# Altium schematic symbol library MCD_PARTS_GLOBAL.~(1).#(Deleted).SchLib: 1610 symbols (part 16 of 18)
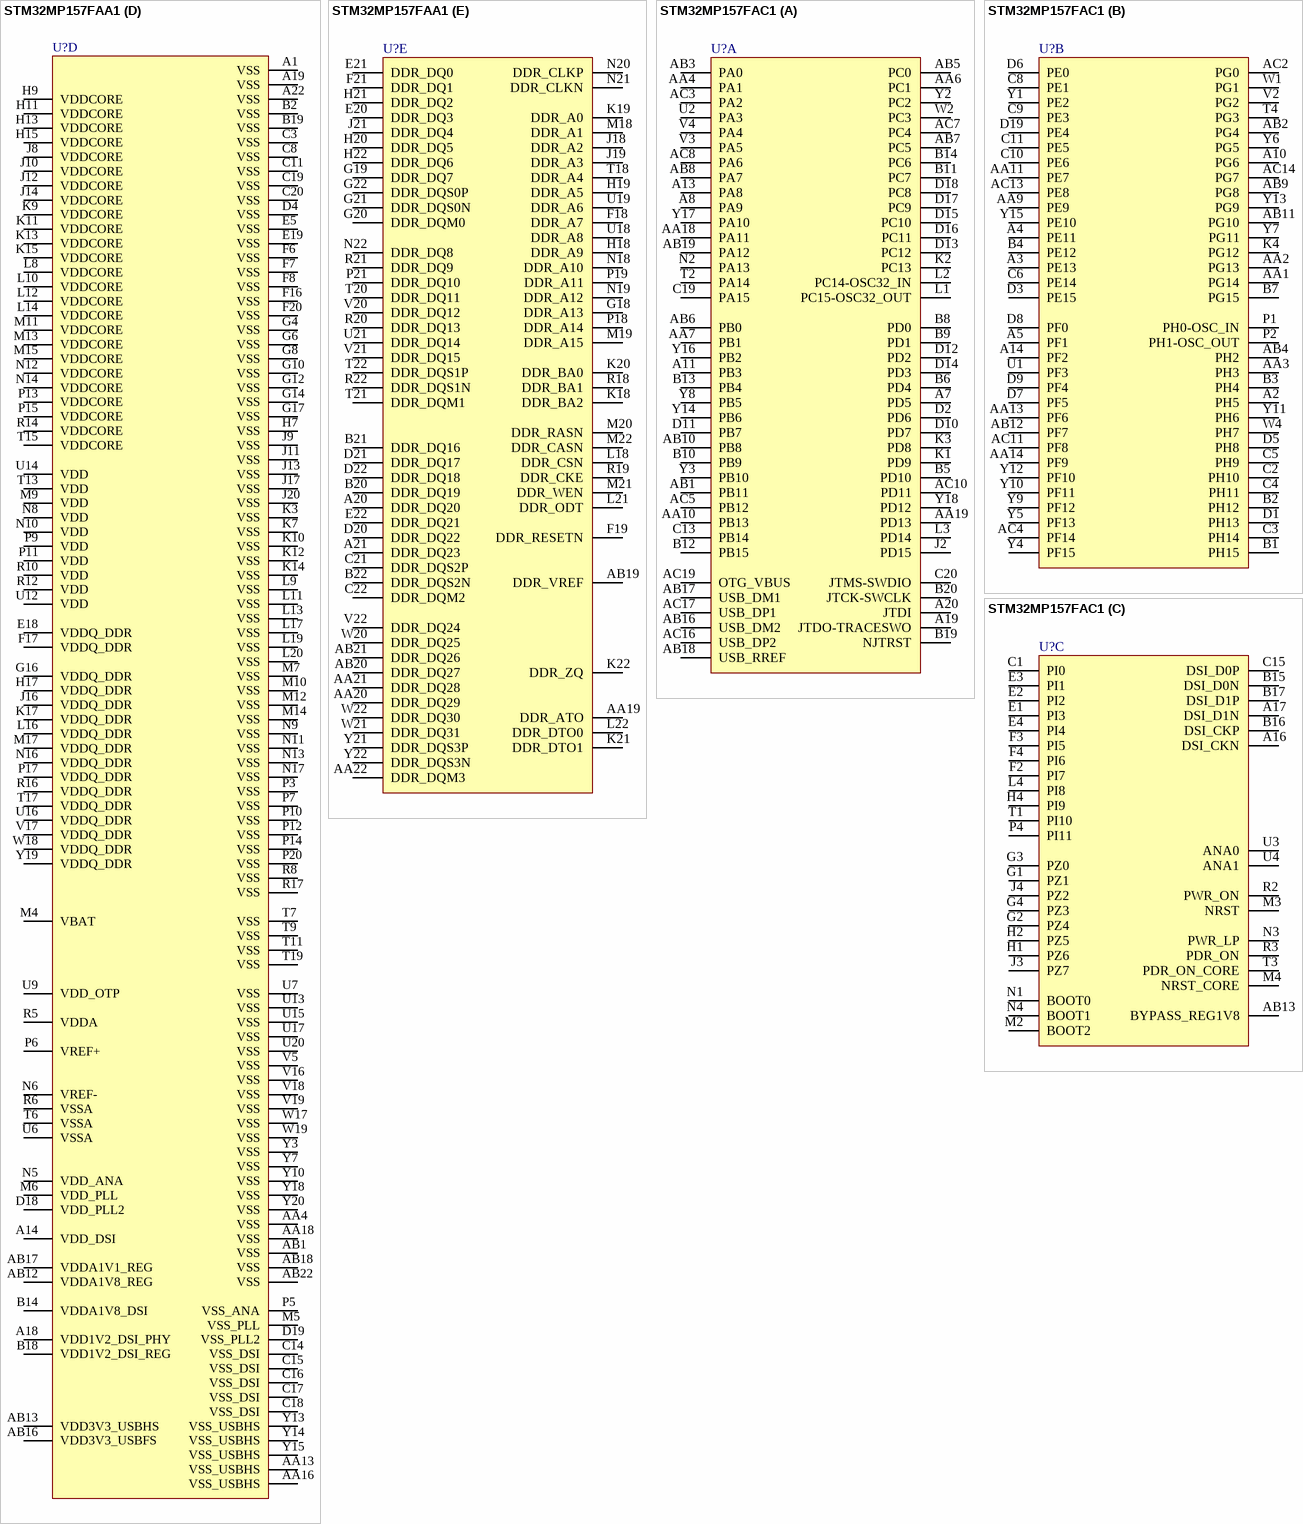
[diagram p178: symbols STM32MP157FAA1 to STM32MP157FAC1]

## STM32MP157FAA1
designator U?
part A pins: A8 PD10, A9 PD5, A11 PA9, A12 PB3, A13 PB14, AA3 PA0, AA5 PB1, AA6 PC5, AA7 PB12, AA8 PB5, AA14 USB_DM2, AA15 USB_DP1, AA17 USB_RREF, AB2 PA2, AB3 PC1, AB5 PB0, AB6 PC4, AB8 PB8, AB9 PD11, AB14 USB_DP2, AB15 USB_DM1, B10 PD1, B11 PD3, B12 PB15, B13 PA8, C9 PD4, C10 PD0, C13 PB4, D12 PD2, D13 PC7, D14 PC9, D15 PC11, D16 JTDI, D17 JTCK-SWCLK, E11 PA15, E12 PC12, E13 PC6, E14 PC8, E15 NJTRST, E16 JTDO-TRACESWO, E17 JTMS-SWDIO, F10 PD7, F11 PB7, F12 PB9, F14 PC10, L1 PD15, L3 PD6, M1 PD8, M2 PD9, M3 PD14, N2 PC13, P1 PC14-OSC32_IN, P2 PC15-OSC32_OUT, R3 PA14, T4 PA3, U3 PC3, U5 PA5, U10 PC0, V4 PA1, V6 PA4, V9 PB10, V10 PB13, V13 PB2, V14 PD13, V15 USBO_VBUS, W3 PA13, W9 PA6, W12 PD12, W13 PB6, W16 PA12, Y1 PC2, Y5 PB11, Y9 PA7, Y16 PA11, Y17 PA10
part B pins: A2 PH5, A3 PH4, A4 PE13, A10 PE3, AA1 PG13, AA2 PG14, AA9 PG10, AA10 PF7, AA11 PF6, AB4 PG4, AB7 PH2, AB10 PF8, AB11 PF9, B1 PH10, B3 PH11, B4 PE14, B9 PF1, C1 PH15, C2 PH14, C4 PE15, C5 PE0, C12 PE5, D3 PH13, D5 PE11, D6 PH8, D7 PE1, D9 PF5, D10 PG15, D11 PG6, E4 PE12, E6 PH9, E9 PE6, E10 PF0, F5 PH12, F9 PF4, F13 PF2, F15 PE4, J4 PG12, T1 PH0-OSC_IN, T2 PH1-OSC_OUT, U4 PG3, U8 PG5, U11 PG11, V3 PF3, V7 PF14, V8 PF12, V11 PH6, V12 PF10, W2 PH7, W4 PG2, W5 PG0, W6 PF15, W7 PF13, W8 PF11, W10 PE7, W11 PE9, W14 PE10, W15 PG9, Y2 PE2, Y4 PG1, Y6 PH3, Y8 PG8, Y11 PG7, Y12 PE8
part C pins: A5 PK6, A6 PK4, A7 PJ13, A15 DSI_D0_N, A16 DSI_CK_N, A17 DSI_D1_N, AA12 BYPASS_REG1V8, B5 PK7, B6 PK3, B7 PJ14, B8 PJ12, B15 DSI_D0_P, B16 DSI_CK_P, B17 DSI_D1_P, C6 PK5, C7 PJ15, D1 PI0, D2 PI14, D8 PK0, E1 PI2, E2 PI1, E3 PI3, E7 PK1, E8 PK2, F1 PI7, F2 PI5, F3 PI15, F4 PZ3, G1 PZ4, G2 PZ0, G3 PZ6, G5 PI6, H1 PI13, H2 PI12, H3 PZ7, H4 PZ5, H5 PZ1, H6 PJ8, J1 PJ3, J2 PJ0, J3 PJ10, J5 PI9, J6 PI4, K1 PJ5, K2 PJ4, K4 PJ2, K5 PZ2, K6 PJ11, L2 PJ9, L4 PJ7, L5 PJ6, L6 PJ1, N1 PI8, N3 BOOT0, N4 BOOT1, P4 BOOT2, R1 NRST_CORE, R2 NRST, R4 ANA0, T3 PI11, T5 ANA1, U1 PWR_LP, U2 PDR_ON_CORE, V1 PWR_ON, V2 PDR_ON, W1 PI10
part D pins: A1 VSS, A14 VDD_DSI, A18 VDD1V2_DSI_PHY, A19 VSS, A22 VSS, AA4 VSS, AA13 VSS_USBHS, AA16 VSS_USBHS, AA18 VSS, AB1 VSS, AB12 VDDA1V8_REG, AB13 VDD3V3_USBHS, AB16 VDD3V3_USBFS, AB17 VDDA1V1_REG, AB18 VSS, AB22 VSS, B2 VSS, B14 VDDA1V8_DSI, B18 VDD1V2_DSI_REG, B19 VSS, C3 VSS, C8 VSS, C11 VSS, C14 VSS_DSI, C15 VSS_DSI, C16 VSS_DSI, C17 VSS_DSI, C18 VSS_DSI, C19 VSS, C20 VSS, D4 VSS, D18 VDD_PLL2, D19 VSS_PLL2, E5 VSS, E18 VDDQ_DDR, E19 VSS, F6 VSS, F7 VSS, F8 VSS, F16 VSS, F17 VDDQ_DDR, F20 VSS, G4 VSS, G6 VSS, G8 VSS, G10 VSS, G12 VSS, G14 VSS, G16 VDDQ_DDR, G17 VSS, H7 VSS, H9 VDDCORE, H11 VDDCORE, H13 VDDCORE, H15 VDDCORE, H17 VDDQ_DDR, J8 VDDCORE, J9 VSS, J10 VDDCORE, J11 VSS, J12 VDDCORE, J13 VSS, J14 VDDCORE, J16 VDDQ_DDR, J17 VSS, J20 VSS, K3 VSS, K7 VSS, K9 VDDCORE, K10 VSS, K11 VDDCORE, K12 VSS, K13 VDDCORE, K14 VSS, K15 VDDCORE, K17 VDDQ_DDR, L8 VDDCORE, L9 VSS, L10 VDDCORE, L11 VSS, L12 VDDCORE, L13 VSS, L14 VDDCORE, L16 VDDQ_DDR, L17 VSS, L19 VSS, L20 VSS, M4 VBAT, M5 VSS_PLL, M6 VDD_PLL, M7 VSS, M9 VDD, M10 VSS, M11 VDDCORE, M12 VSS, M13 VDDCORE, M14 VSS, M15 VDDCORE, M17 VDDQ_DDR, N5 VDD_ANA, N6 VREF-, N8 VDD, N9 VSS, N10 VDD, N11 VSS, N12 VDDCORE, N13 VSS, N14 VDDCORE, N16 VDDQ_DDR, N17 VSS, P3 VSS, P5 VSS_ANA, P6 VREF+, P7 VSS, P9 VDD, P10 VSS, P11 VDD, P12 VSS, P13 VDDCORE, P14 VSS, P15 VDDCORE, P17 VDDQ_DDR, P20 VSS, R5 VDDA, R6 VSSA, R8 VSS, R10 VDD, R12 VDD, R14 VDDCORE, R16 VDDQ_DDR, R17 VSS, T6 VSSA, T7 VSS, T9 VSS, T11 VSS, T13 VDD, T15 VDDCORE, T17 VDDQ_DDR, T19 VSS, U6 VSSA, U7 VSS, U9 VDD_OTP, U12 VDD, U13 VSS, U14 VDD, U15 VSS, U16 VDDQ_DDR, U17 VSS, U20 VSS, V5 VSS, V16 VSS, V17 VDDQ_DDR, V18 VSS, V19 VSS, W17 VSS, W18 VDDQ_DDR, W19 VSS, Y3 VSS, Y7 VSS, Y10 VSS, Y13 VSS_USBHS, Y14 VSS_USBHS, Y15 VSS_USBHS, Y18 VSS, Y19 VDDQ_DDR, Y20 VSS
part E pins: A20 DDR_DQ20, A21 DDR_DQ23, AA19 DDR_ATO, AA20 DDR_DQ29, AA21 DDR_DQ28, AA22 DDR_DQM3, AB19 DDR_VREF, AB20 DDR_DQ27, AB21 DDR_DQ26, B20 DDR_DQ19, B21 DDR_DQ16, B22 DDR_DQS2N, C21 DDR_DQS2P, C22 DDR_DQM2, D20 DDR_DQ22, D21 DDR_DQ17, D22 DDR_DQ18, E20 DDR_DQ3, E21 DDR_DQ0, E22 DDR_DQ21, F18 DDR_A7, F19 DDR_RESETN, F21 DDR_DQ1, G18 DDR_A13, G19 DDR_DQ7, G20 DDR_DQM0, G21 DDR_DQS0N, G22 DDR_DQS0P, H18 DDR_A9, H19 DDR_A5, H20 DDR_DQ5, H21 DDR_DQ2, H22 DDR_DQ6, J18 DDR_A2, J19 DDR_A3, J21 DDR_DQ4, K18 DDR_BA2, K19 DDR_A0, K20 DDR_BA0, K21 DDR_DTO1, K22 DDR_ZQ, L18 DDR_CSN, L21 DDR_ODT, L22 DDR_DTO0, M18 DDR_A1, M19 DDR_A15, M20 DDR_RASN, M21 DDR_WEN, M22 DDR_CASN, N18 DDR_A10, N19 DDR_A12, N20 DDR_CLKP, N21 DDR_CLKN, N22 DDR_DQ8, P18 DDR_A14, P19 DDR_A11, P21 DDR_DQ10, R18 DDR_BA1, R19 DDR_CKE, R20 DDR_DQ13, R21 DDR_DQ9, R22 DDR_DQS1N, T18 DDR_A4, T20 DDR_DQ11, T21 DDR_DQM1, T22 DDR_DQS1P, U18 DDR_A8, U19 DDR_A6, U21 DDR_DQ14, V20 DDR_DQ12, V21 DDR_DQ15, V22 DDR_DQ24, W20 DDR_DQ25, W21 DDR_DQ31, W22 DDR_DQ30, Y21 DDR_DQS3P, Y22 DDR_DQS3N

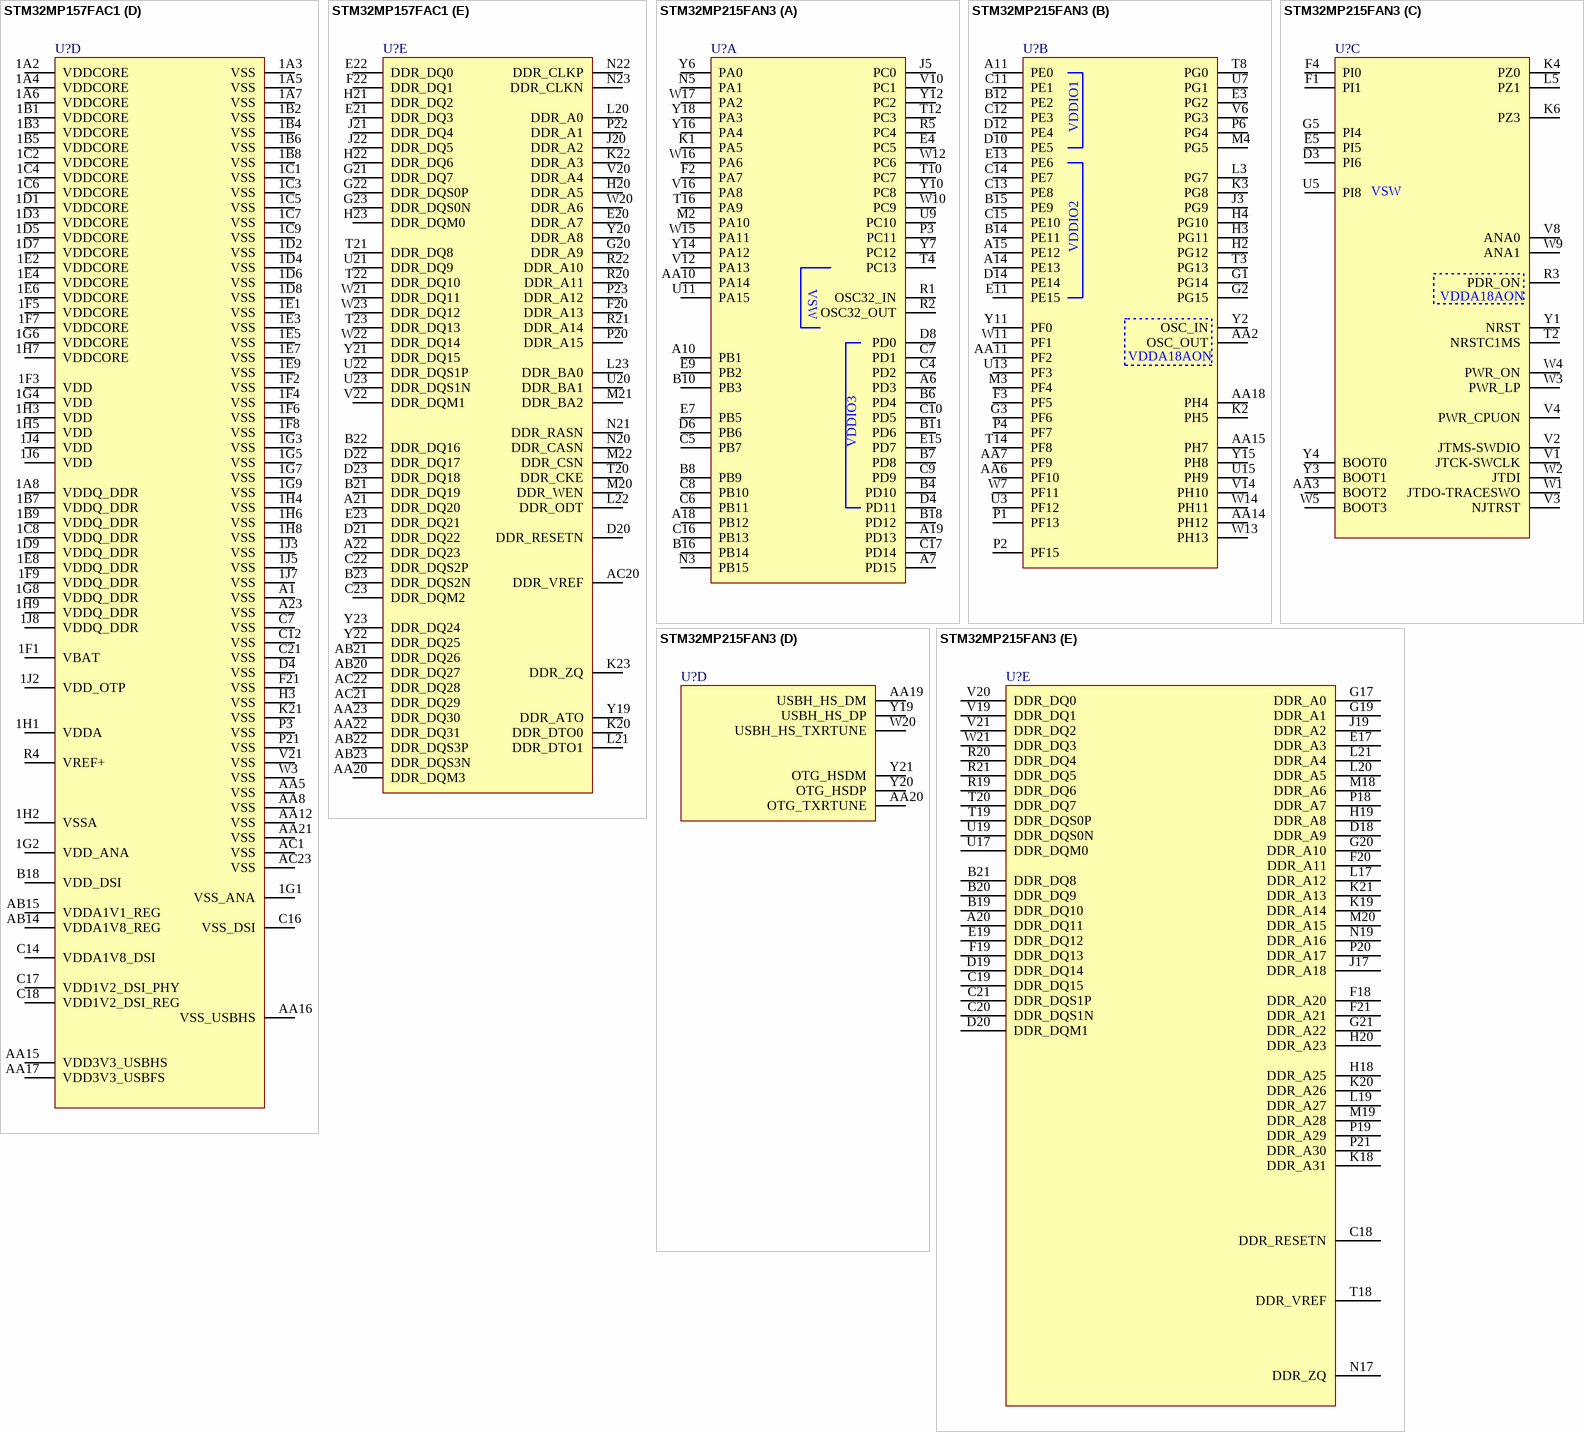
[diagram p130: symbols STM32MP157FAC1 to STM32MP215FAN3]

## STM32MP157FAC1
designator U?
part A pins: A7 PD5, A8 PA9, A11 PB3, A13 PA8, A19 JTDO-TRACESWO, A20 JTDI, AA4 PA1, AA6 PC1, AA7 PB1, AA10 PB13, AA18 PA11, AA19 PD13, AB1 PB11, AB3 PA0, AB5 PC0, AB6 PB0, AB7 PC5, AB8 PA7, AB10 PB8, AB16 USB_DM2, AB17 USB_DM1, AB18 USB_RREF, AB19 PA12, AC3 PA2, AC5 PB12, AC7 PC4, AC8 PA6, AC10 PD11, AC16 USB_DP2, AC17 USB_DP1, AC19 OTG_VBUS, B5 PD10, B6 PD4, B8 PD0, B9 PD1, B10 PB9, B11 PC7, B12 PB15, B13 PB4, B14 PC6, B19 NJTRST, B20 JTCK-SWCLK, C13 PB14, C19 PA15, C20 JTMS-SWDIO, D2 PD6, D10 PD7, D11 PB7, D12 PD2, D13 PC12, D14 PD3, D15 PC10, D16 PC11, D17 PC9, D18 PC8, J2 PD15, K1 PD9, K2 PC13, K3 PD8, L1 PC15-OSC32_OUT, L2 PC14-OSC32_IN, L3 PD14, N2 PA13, T2 PA14, U2 PA3, V3 PA5, V4 PA4, W2 PC3, Y2 PC2, Y3 PB10, Y8 PB5, Y14 PB6, Y16 PB2, Y17 PA10, Y18 PD12
part B pins: A2 PH5, A3 PE13, A4 PE11, A5 PF1, A10 PG6, A14 PF2, AA1 PG14, AA2 PG13, AA3 PH3, AA9 PE9, AA11 PE7, AA13 PF6, AA14 PF9, AB2 PG4, AB4 PH2, AB9 PG8, AB11 PG10, AB12 PF7, AC2 PG0, AC4 PF14, AC11 PF8, AC13 PE8, AC14 PG7, B1 PH15, B2 PH12, B3 PH4, B4 PE12, B7 PG15, C2 PH10, C3 PH14, C4 PH11, C5 PH9, C6 PE14, C8 PE1, C9 PE3, C10 PE6, C11 PE5, D1 PH13, D3 PE15, D5 PH8, D6 PE0, D7 PF5, D8 PF0, D9 PF4, D19 PE4, K4 PG12, P1 PH0-OSC_IN, P2 PH1-OSC_OUT, T4 PG3, U1 PF3, V2 PG2, W1 PG1, W4 PH7, Y1 PE2, Y4 PF15, Y5 PF13, Y6 PG5, Y7 PG11, Y9 PF12, Y10 PF11, Y11 PH6, Y12 PF10, Y13 PG9, Y15 PE10
part C pins: A16 DSI_CKN, A17 DSI_D1N, AB13 BYPASS_REG1V8, B15 DSI_D0N, B16 DSI_CKP, B17 DSI_D1P, C1 PI0, C15 DSI_D0P, E1 PI3, E2 PI2, E3 PI1, E4 PI4, F2 PI7, F3 PI5, F4 PI6, G1 PZ1, G2 PZ4, G3 PZ0, G4 PZ3, H1 PZ6, H2 PZ5, H4 PI9, J3 PZ7, J4 PZ2, L4 PI8, M2 BOOT2, M3 NRST, M4 NRST_CORE, N1 BOOT0, N3 PWR_LP, N4 BOOT1, P4 PI11, R2 PWR_ON, R3 PDR_ON, T1 PI10, T3 PDR_ON_CORE, U3 ANA0, U4 ANA1
part D pins: 1A2 VDDCORE, 1A3 VSS, 1A4 VDDCORE, 1A5 VSS, 1A6 VDDCORE, 1A7 VSS, 1A8 VDDQ_DDR, 1B1 VDDCORE, 1B2 VSS, 1B3 VDDCORE, 1B4 VSS, 1B5 VDDCORE, 1B6 VSS, 1B7 VDDQ_DDR, 1B8 VSS, 1B9 VDDQ_DDR, 1C1 VSS, 1C2 VDDCORE, 1C3 VSS, 1C4 VDDCORE, 1C5 VSS, 1C6 VDDCORE, 1C7 VSS, 1C8 VDDQ_DDR, 1C9 VSS, 1D1 VDDCORE, 1D2 VSS, 1D3 VDDCORE, 1D4 VSS, 1D5 VDDCORE, 1D6 VSS, 1D7 VDDCORE, 1D8 VSS, 1D9 VDDQ_DDR, 1E1 VSS, 1E2 VDDCORE, 1E3 VSS, 1E4 VDDCORE, 1E5 VSS, 1E6 VDDCORE, 1E7 VSS, 1E8 VDDQ_DDR, 1E9 VSS, 1F1 VBAT, 1F2 VSS, 1F3 VDD, 1F4 VSS, 1F5 VDDCORE, 1F6 VSS, 1F7 VDDCORE, 1F8 VSS, 1F9 VDDQ_DDR, 1G1 VSS_ANA, 1G2 VDD_ANA, 1G3 VSS, 1G4 VDD, 1G5 VSS, 1G6 VDDCORE, 1G7 VSS, 1G8 VDDQ_DDR, 1G9 VSS, 1H1 VDDA, 1H2 VSSA, 1H3 VDD, 1H4 VSS, 1H5 VDD, 1H6 VSS, 1H7 VDDCORE, 1H8 VSS, 1H9 VDDQ_DDR, 1J2 VDD_OTP, 1J3 VSS, 1J4 VDD, 1J5 VSS, 1J6 VDD, 1J7 VSS, 1J8 VDDQ_DDR, A1 VSS, A23 VSS, AA5 VSS, AA8 VSS, AA12 VSS, AA15 VDD3V3_USBHS, AA16 VSS_USBHS, AA17 VDD3V3_USBFS, AA21 VSS, AB14 VDDA1V8_REG, AB15 VDDA1V1_REG, AC1 VSS, AC23 VSS, B18 VDD_DSI, C7 VSS, C12 VSS, C14 VDDA1V8_DSI, C16 VSS_DSI, C17 VDD1V2_DSI_PHY, C18 VDD1V2_DSI_REG, C21 VSS, D4 VSS, F21 VSS, H3 VSS, K21 VSS, P3 VSS, P21 VSS, R4 VREF+, V21 VSS, W3 VSS
part E pins: A21 DDR_DQ20, A22 DDR_DQ23, AA20 DDR_DQM3, AA22 DDR_DQ31, AA23 DDR_DQ30, AB20 DDR_DQ27, AB21 DDR_DQ26, AB22 DDR_DQS3P, AB23 DDR_DQS3N, AC20 DDR_VREF, AC21 DDR_DQ29, AC22 DDR_DQ28, B21 DDR_DQ19, B22 DDR_DQ16, B23 DDR_DQS2N, C22 DDR_DQS2P, C23 DDR_DQM2, D20 DDR_RESETN, D21 DDR_DQ22, D22 DDR_DQ17, D23 DDR_DQ18, E20 DDR_A7, E21 DDR_DQ3, E22 DDR_DQ0, E23 DDR_DQ21, F20 DDR_A13, F22 DDR_DQ1, G20 DDR_A9, G21 DDR_DQ7, G22 DDR_DQS0P, G23 DDR_DQS0N, H20 DDR_A5, H21 DDR_DQ2, H22 DDR_DQ6, H23 DDR_DQM0, J20 DDR_A2, J21 DDR_DQ4, J22 DDR_DQ5, K20 DDR_DTO0, K22 DDR_A3, K23 DDR_ZQ, L20 DDR_A0, L21 DDR_DTO1, L22 DDR_ODT, L23 DDR_BA0, M20 DDR_WEN, M21 DDR_BA2, M22 DDR_CSN, N20 DDR_CASN, N21 DDR_RASN, N22 DDR_CLKP, N23 DDR_CLKN, P20 DDR_A15, P22 DDR_A1, P23 DDR_A12, R20 DDR_A11, R21 DDR_A14, R22 DDR_A10, T20 DDR_CKE, T21 DDR_DQ8, T22 DDR_DQ10, T23 DDR_DQ13, U20 DDR_BA1, U21 DDR_DQ9, U22 DDR_DQS1P, U23 DDR_DQS1N, V20 DDR_A4, V22 DDR_DQM1, W20 DDR_A6, W21 DDR_DQ11, W22 DDR_DQ14, W23 DDR_DQ12, Y19 DDR_ATO, Y20 DDR_A8, Y21 DDR_DQ15, Y22 DDR_DQ25, Y23 DDR_DQ24

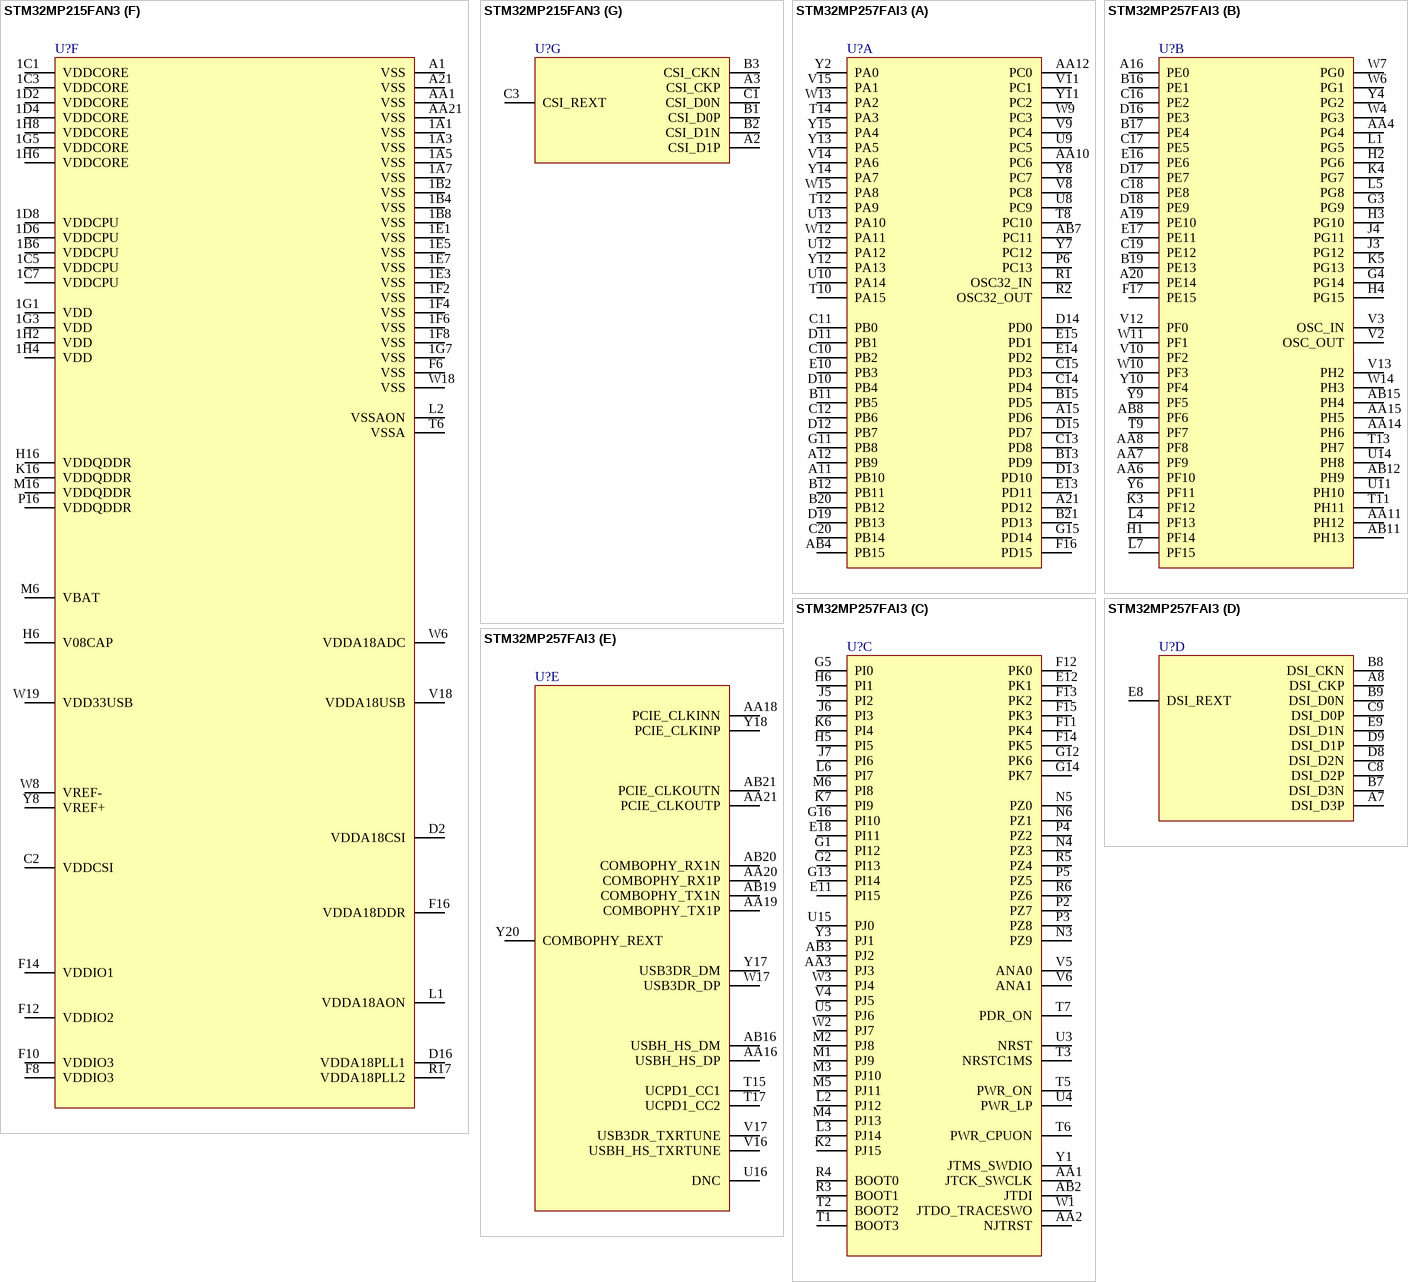
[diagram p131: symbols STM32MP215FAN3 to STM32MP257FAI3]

## STM32MP215FAN3
designator U?
part A pins: A6 PD3, A7 PD15, A10 PB1, A18 PB12, A19 PD13, AA10 PA14, B4 PD10, B6 PD4, B7 PD8, B8 PB9, B10 PB3, B11 PD6, B16 PB14, B18 PD12, C4 PD2, C5 PB7, C6 PB11, C7 PD1, C8 PB10, C9 PD9, C10 PD5, C16 PB13, C17 PD14, D4 PD11, D6 PB6, D8 PD0, E4 PC5, E7 PB5, E9 PB2, E15 PD7, F2 PA7, J5 PC0, K1 PA5, M2 PA10, N3 PB15, N5 PA1, P3 PC11, R1 OSC32_IN, R2 OSC32_OUT, R5 PC4, T4 PC13, T10 PC7, T12 PC3, T16 PA9, U9 PC10, U11 PA15, V10 PC1, V12 PA13, V16 PA8, W10 PC9, W12 PC6, W15 PA11, W16 PA6, W17 PA2, Y6 PA0, Y7 PC12, Y10 PC8, Y12 PC2, Y14 PA12, Y16 PA4, Y18 PA3
part B pins: A11 PE0, A14 PE13, A15 PE12, AA2 OSC_OUT, AA6 PF10, AA7 PF9, AA11 PF2, AA14 PH12, AA15 PH7, AA18 PH4, B12 PE2, B14 PE11, B15 PE9, C11 PE1, C12 PE3, C13 PE8, C14 PE7, C15 PE10, D10 PE5, D12 PE4, D14 PE14, E3 PG2, E11 PE15, E13 PE6, F3 PF5, G1 PG14, G2 PG15, G3 PF6, H2 PG12, H3 PG11, H4 PG10, J3 PG9, K2 PH5, K3 PG8, L3 PG7, M3 PF4, M4 PG5, P1 PF13, P2 PF15, P4 PF7, P6 PG4, T3 PG13, T8 PG0, T14 PF8, U3 PF12, U7 PG1, U13 PF3, U15 PH9, V6 PG3, V14 PH10, W7 PF11, W11 PF1, W13 PH13, W14 PH11, Y2 OSC_IN, Y11 PF0, Y15 PH8
part C pins: AA3 BOOT2, D3 PI6, E5 PI5, F1 PI1, F4 PI0, G5 PI4, K4 PZ0, K6 PZ3, L5 PZ1, R3 PDR_ON, T2 NRSTC1MS, U5 PI8, V1 JTCK-SWCLK, V2 JTMS-SWDIO, V3 NJTRST, V4 PWR_CPUON, V8 ANA0, W1 JTDO-TRACESWO, W2 JTDI, W3 PWR_LP, W4 PWR_ON, W5 BOOT3, W9 ANA1, Y1 NRST, Y3 BOOT1, Y4 BOOT0
part D pins: AA19 USBH_HS_DM, AA20 OTG_TXRTUNE, W20 USBH_HS_TXRTUNE, Y19 USBH_HS_DP, Y20 OTG_HSDP, Y21 OTG_HSDM
part E pins: A20 DDR_DQ11, B19 DDR_DQ10, B20 DDR_DQ9, B21 DDR_DQ8, C18 DDR_RESETN, C19 DDR_DQ15, C20 DDR_DQS1N, C21 DDR_DQS1P, D18 DDR_A9, D19 DDR_DQ14, D20 DDR_DQM1, E17 DDR_A3, E19 DDR_DQ12, F18 DDR_A20, F19 DDR_DQ13, F20 DDR_A11, F21 DDR_A21, G17 DDR_A0, G19 DDR_A1, G20 DDR_A10, G21 DDR_A22, H18 DDR_A25, H19 DDR_A8, H20 DDR_A23, J17 DDR_A18, J19 DDR_A2, K18 DDR_A31, K19 DDR_A14, K20 DDR_A26, K21 DDR_A13, L17 DDR_A12, L19 DDR_A27, L20 DDR_A5, L21 DDR_A4, M18 DDR_A6, M19 DDR_A28, M20 DDR_A15, N17 DDR_ZQ, N19 DDR_A16, P18 DDR_A7, P19 DDR_A29, P20 DDR_A17, P21 DDR_A30, R19 DDR_DQ6, R20 DDR_DQ4, R21 DDR_DQ5, T18 DDR_VREF, T19 DDR_DQS0P, T20 DDR_DQ7, U17 DDR_DQM0, U19 DDR_DQS0N, V19 DDR_DQ1, V20 DDR_DQ0, V21 DDR_DQ2, W21 DDR_DQ3
part F pins: 1A1 VSS, 1A3 VSS, 1A5 VSS, 1A7 VSS, 1B2 VSS, 1B4 VSS, 1B6 VDDCPU, 1B8 VSS, 1C1 VDDCORE, 1C3 VDDCORE, 1C5 VDDCPU, 1C7 VDDCPU, 1D2 VDDCORE, 1D4 VDDCORE, 1D6 VDDCPU, 1D8 VDDCPU, 1E1 VSS, 1E3 VSS, 1E5 VSS, 1E7 VSS, 1F2 VSS, 1F4 VSS, 1F6 VSS, 1F8 VSS, 1G1 VDD, 1G3 VDD, 1G5 VDDCORE, 1G7 VSS, 1H2 VDD, 1H4 VDD, 1H6 VDDCORE, 1H8 VDDCORE, A1 VSS, A21 VSS, AA1 VSS, AA21 VSS, C2 VDDCSI, D2 VDDA18CSI, D16 VDDA18PLL1, F6 VSS, F8 VDDIO3, F10 VDDIO3, F12 VDDIO2, F14 VDDIO1, F16 VDDA18DDR, H6 V08CAP, H16 VDDQDDR, K16 VDDQDDR, L1 VDDA18AON, L2 VSSAON, M6 VBAT, M16 VDDQDDR, P16 VDDQDDR, R17 VDDA18PLL2, T6 VSSA, V18 VDDA18USB, W6 VDDA18ADC, W8 VREF-, W18 VSS, W19 VDD33USB, Y8 VREF+
part G pins: A2 CSI_D1P, A3 CSI_CKP, B1 CSI_D0P, B2 CSI_D1N, B3 CSI_CKN, C1 CSI_D0N, C3 CSI_REXT

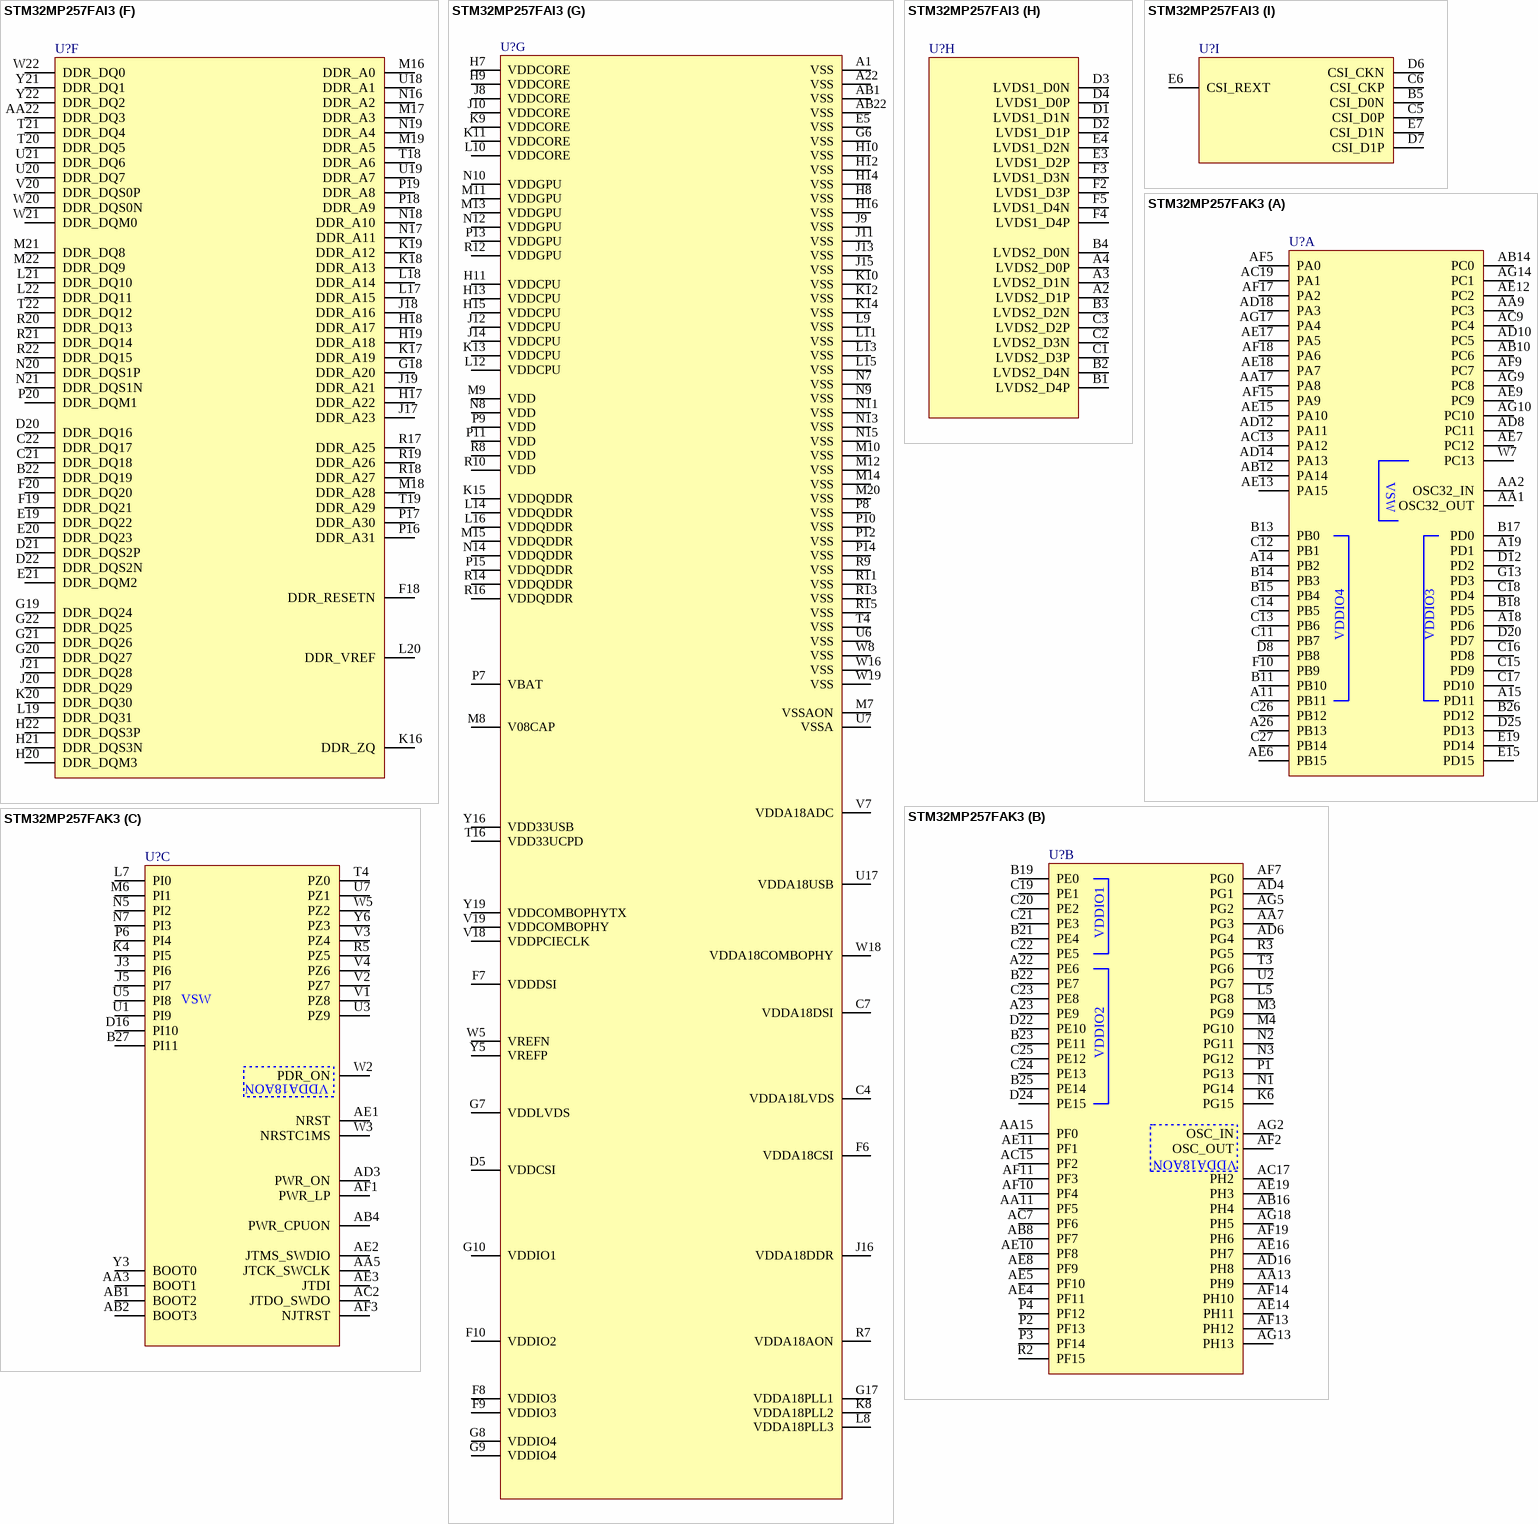
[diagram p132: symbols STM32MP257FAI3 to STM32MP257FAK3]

## STM32MP257FAI3
designator U?
part A pins: A11 PB10, A12 PB9, A15 PD6, A21 PD12, AA10 PC6, AA12 PC0, AB4 PB15, AB7 PC11, B11 PB5, B12 PB11, B13 PD9, B15 PD5, B20 PB12, B21 PD13, C10 PB2, C11 PB0, C12 PB6, C13 PD8, C14 PD4, C15 PD3, C20 PB14, D10 PB4, D11 PB1, D12 PB7, D13 PD10, D14 PD0, D15 PD7, D19 PB13, E10 PB3, E13 PD11, E14 PD2, E15 PD1, F16 PD15, G11 PB8, G15 PD14, P6 PC13, R1 OSC32_IN, R2 OSC32_OUT, T8 PC10, T10 PA15, T12 PA9, T14 PA3, U8 PC9, U9 PC5, U10 PA14, U12 PA12, U13 PA10, V8 PC8, V9 PC4, V11 PC1, V14 PA6, V15 PA1, W9 PC3, W12 PA11, W13 PA2, W15 PA8, Y2 PA0, Y7 PC12, Y8 PC7, Y11 PC2, Y12 PA13, Y13 PA5, Y14 PA7, Y15 PA4
part B pins: A16 PE0, A19 PE10, A20 PE14, AA4 PG4, AA6 PF10, AA7 PF9, AA8 PF8, AA11 PH12, AA14 PH6, AA15 PH5, AB8 PF6, AB11 PH13, AB12 PH9, AB15 PH4, B16 PE1, B17 PE4, B19 PE13, C16 PE2, C17 PE5, C18 PE8, C19 PE12, D16 PE3, D17 PE7, D18 PE9, E16 PE6, E17 PE11, F17 PE15, G3 PG9, G4 PG14, H1 PF14, H2 PG6, H3 PG10, H4 PG15, J3 PG12, J4 PG11, K3 PF12, K4 PG7, K5 PG13, L1 PG5, L4 PF13, L5 PG8, L7 PF15, T9 PF7, T11 PH11, T13 PH7, U11 PH10, U14 PH8, V2 OSC_OUT, V3 OSC_IN, V10 PF2, V12 PF0, V13 PH2, W4 PG3, W6 PG1, W7 PG0, W10 PF3, W11 PF1, W14 PH3, Y4 PG2, Y6 PF11, Y9 PF5, Y10 PF4
part C pins: AA1 JTCK_SWCLK, AA2 NJTRST, AA3 PJ3, AB2 JTDI, AB3 PJ2, E11 PI15, E12 PK1, E18 PI11, F11 PK4, F12 PK0, F13 PK2, F14 PK5, F15 PK3, G1 PI12, G2 PI13, G5 PI0, G12 PK6, G13 PI14, G14 PK7, G16 PI10, H5 PI5, H6 PI1, J5 PI2, J6 PI3, J7 PI6, K2 PJ15, K6 PI4, K7 PI9, L2 PJ12, L3 PJ14, L6 PI7, M1 PJ9, M2 PJ8, M3 PJ10, M4 PJ13, M5 PJ11, M6 PI8, N3 PZ9, N4 PZ3, N5 PZ0, N6 PZ1, P2 PZ7, P3 PZ8, P4 PZ2, P5 PZ5, R3 BOOT1, R4 BOOT0, R5 PZ4, R6 PZ6, T1 BOOT3, T2 BOOT2, T3 NRSTC1MS, T5 PWR_ON, T6 PWR_CPUON, T7 PDR_ON, U3 NRST, U4 PWR_LP, U5 PJ6, U15 PJ0, V4 PJ5, V5 ANA0, V6 ANA1, W1 JTDO_TRACESWO, W2 PJ7, W3 PJ4, Y1 JTMS_SWDIO, Y3 PJ1
part D pins: A7 DSI_D3P, A8 DSI_CKP, B7 DSI_D3N, B8 DSI_CKN, B9 DSI_D0N, C8 DSI_D2P, C9 DSI_D0P, D8 DSI_D2N, D9 DSI_D1P, E8 DSI_REXT, E9 DSI_D1N
part E pins: AA16 USBH_HS_DP, AA18 PCIE_CLKINN, AA19 COMBOPHY_TX1P, AA20 COMBOPHY_RX1P, AA21 PCIE_CLKOUTP, AB16 USBH_HS_DM, AB19 COMBOPHY_TX1N, AB20 COMBOPHY_RX1N, AB21 PCIE_CLKOUTN, T15 UCPD1_CC1, T17 UCPD1_CC2, U16 DNC, V16 USBH_HS_TXRTUNE, V17 USB3DR_TXRTUNE, W17 USB3DR_DP, Y17 USB3DR_DM, Y18 PCIE_CLKINP, Y20 COMBOPHY_REXT
part F pins: AA22 DDR_DQ3, B22 DDR_DQ19, C21 DDR_DQ18, C22 DDR_DQ17, D20 DDR_DQ16, D21 DDR_DQS2P, D22 DDR_DQS2N, E19 DDR_DQ22, E20 DDR_DQ23, E21 DDR_DQM2, F18 DDR_RESETN, F19 DDR_DQ21, F20 DDR_DQ20, G18 DDR_A20, G19 DDR_DQ24, G20 DDR_DQ27, G21 DDR_DQ26, G22 DDR_DQ25, H17 DDR_A22, H18 DDR_A17, H19 DDR_A18, H20 DDR_DQM3, H21 DDR_DQS3N, H22 DDR_DQS3P, J17 DDR_A23, J18 DDR_A16, J19 DDR_A21, J20 DDR_DQ29, J21 DDR_DQ28, K16 DDR_ZQ, K17 DDR_A19, K18 DDR_A13, K19 DDR_A12, K20 DDR_DQ30, L17 DDR_A15, L18 DDR_A14, L19 DDR_DQ31, L20 DDR_VREF, L21 DDR_DQ10, L22 DDR_DQ11, M16 DDR_A0, M17 DDR_A3, M18 DDR_A28, M19 DDR_A5, M21 DDR_DQ8, M22 DDR_DQ9, N16 DDR_A2, N17 DDR_A11, N18 DDR_A10, N19 DDR_A4, N20 DDR_DQS1P, N21 DDR_DQS1N, P16 DDR_A31, P17 DDR_A30, P18 DDR_A9, P19 DDR_A8, P20 DDR_DQM1, R17 DDR_A25, R18 DDR_A27, R19 DDR_A26, R20 DDR_DQ13, R21 DDR_DQ14, R22 DDR_DQ15, T18 DDR_A6, T19 DDR_A29, T20 DDR_DQ5, T21 DDR_DQ4, T22 DDR_DQ12, U18 DDR_A1, U19 DDR_A7, U20 DDR_DQ7, U21 DDR_DQ6, V20 DDR_DQS0P, W20 DDR_DQS0N, W21 DDR_DQM0, W22 DDR_DQ0, Y21 DDR_DQ1, Y22 DDR_DQ2
part G pins: A1 VSS, A22 VSS, AB1 VSS, AB22 VSS, C4 VDDA18LVDS, C7 VDDA18DSI, D5 VDDCSI, E5 VSS, F6 VDDA18CSI, F7 VDDDSI, F8 VDDIO3, F9 VDDIO3, F10 VDDIO2, G6 VSS, G7 VDDLVDS, G8 VDDIO4, G9 VDDIO4, G10 VDDIO1, G17 VDDA18PLL1, H7 VDDCORE, H8 VSS, H9 VDDCORE, H10 VSS, H11 VDDCPU, H12 VSS, H13 VDDCPU, H14 VSS, H15 VDDCPU, H16 VSS, J8 VDDCORE, J9 VSS, J10 VDDCORE, J11 VSS, J12 VDDCPU, J13 VSS, J14 VDDCPU, J15 VSS, J16 VDDA18DDR, K8 VDDA18PLL2, K9 VDDCORE, K10 VSS, K11 VDDCORE, K12 VSS, K13 VDDCPU, K14 VSS, K15 VDDQDDR, L8 VDDA18PLL3, L9 VSS, L10 VDDCORE, L11 VSS, L12 VDDCPU, L13 VSS, L14 VDDQDDR, L15 VSS, L16 VDDQDDR, M7 VSSAON, M8 V08CAP, M9 VDD, M10 VSS, M11 VDDGPU, M12 VSS, M13 VDDGPU, M14 VSS, M15 VDDQDDR, M20 VSS, N7 VSS, N8 VDD, N9 VSS, N10 VDDGPU, N11 VSS, N12 VDDGPU, N13 VSS, N14 VDDQDDR, N15 VSS, P7 VBAT, P8 VSS, P9 VDD, P10 VSS, P11 VDD, P12 VSS, P13 VDDGPU, P14 VSS, P15 VDDQDDR, R7 VDDA18AON, R8 VDD, R9 VSS, R10 VDD, R11 VSS, R12 VDDGPU, R13 VSS, R14 VDDQDDR, R15 VSS, R16 VDDQDDR, T4 VSS, T16 VDD33UCPD, U6 VSS, U7 VSSA, U17 VDDA18USB, V7 VDDA18ADC, V18 VDDPCIECLK, V19 VDDCOMBOPHY, W5 VREFN, W8 VSS, W16 VSS, W18 VDDA18COMBOPHY, W19 VSS, Y5 VREFP, Y16 VDD33USB, Y19 VDDCOMBOPHYTX
part H pins: A2 LVDS2_D1P, A3 LVDS2_D1N, A4 LVDS2_D0P, B1 LVDS2_D4P, B2 LVDS2_D4N, B3 LVDS2_D2N, B4 LVDS2_D0N, C1 LVDS2_D3P, C2 LVDS2_D3N, C3 LVDS2_D2P, D1 LVDS1_D1N, D2 LVDS1_D1P, D3 LVDS1_D0N, D4 LVDS1_D0P, E3 LVDS1_D2P, E4 LVDS1_D2N, F2 LVDS1_D3P, F3 LVDS1_D3N, F4 LVDS1_D4P, F5 LVDS1_D4N
part I pins: B5 CSI_D0N, C5 CSI_D0P, C6 CSI_CKP, D6 CSI_CKN, D7 CSI_D1P, E6 CSI_REXT, E7 CSI_D1N
1 alternate drawing of the same symbol

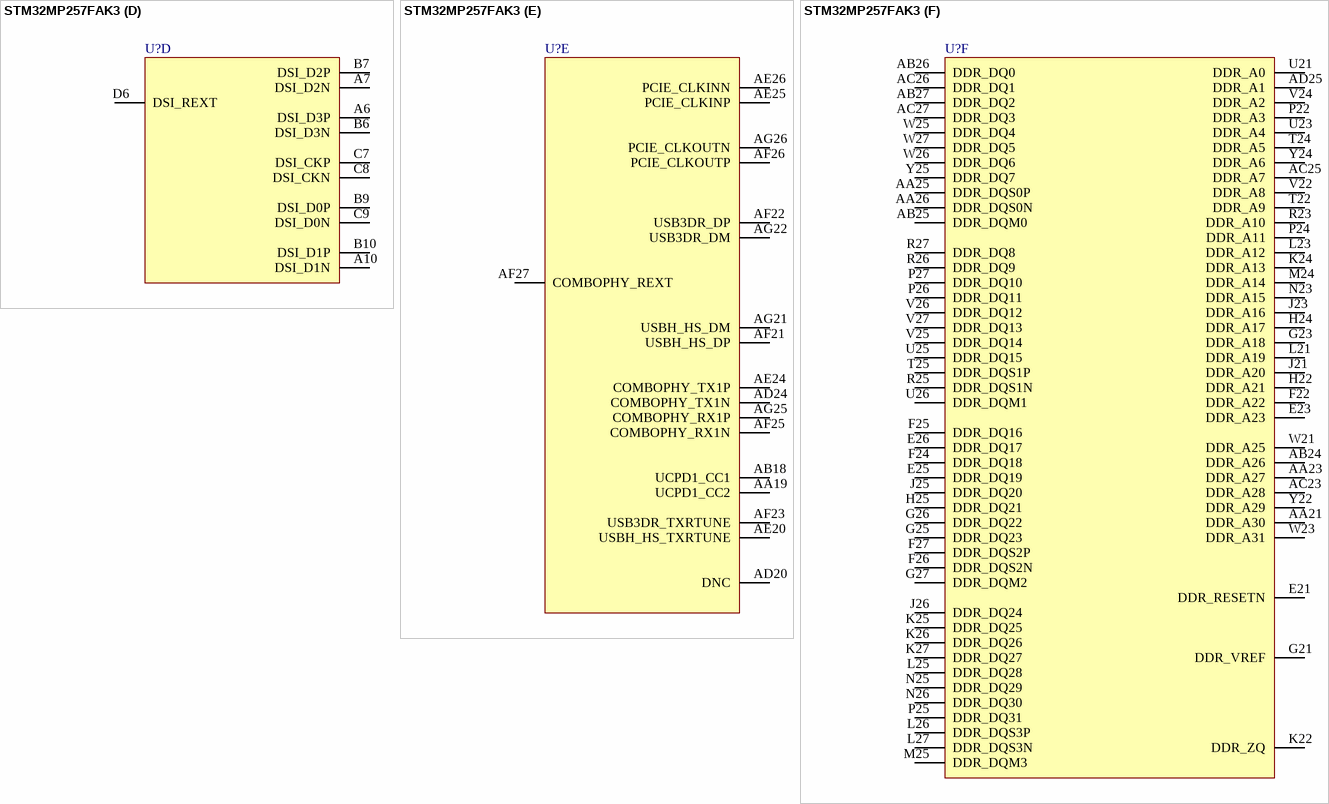
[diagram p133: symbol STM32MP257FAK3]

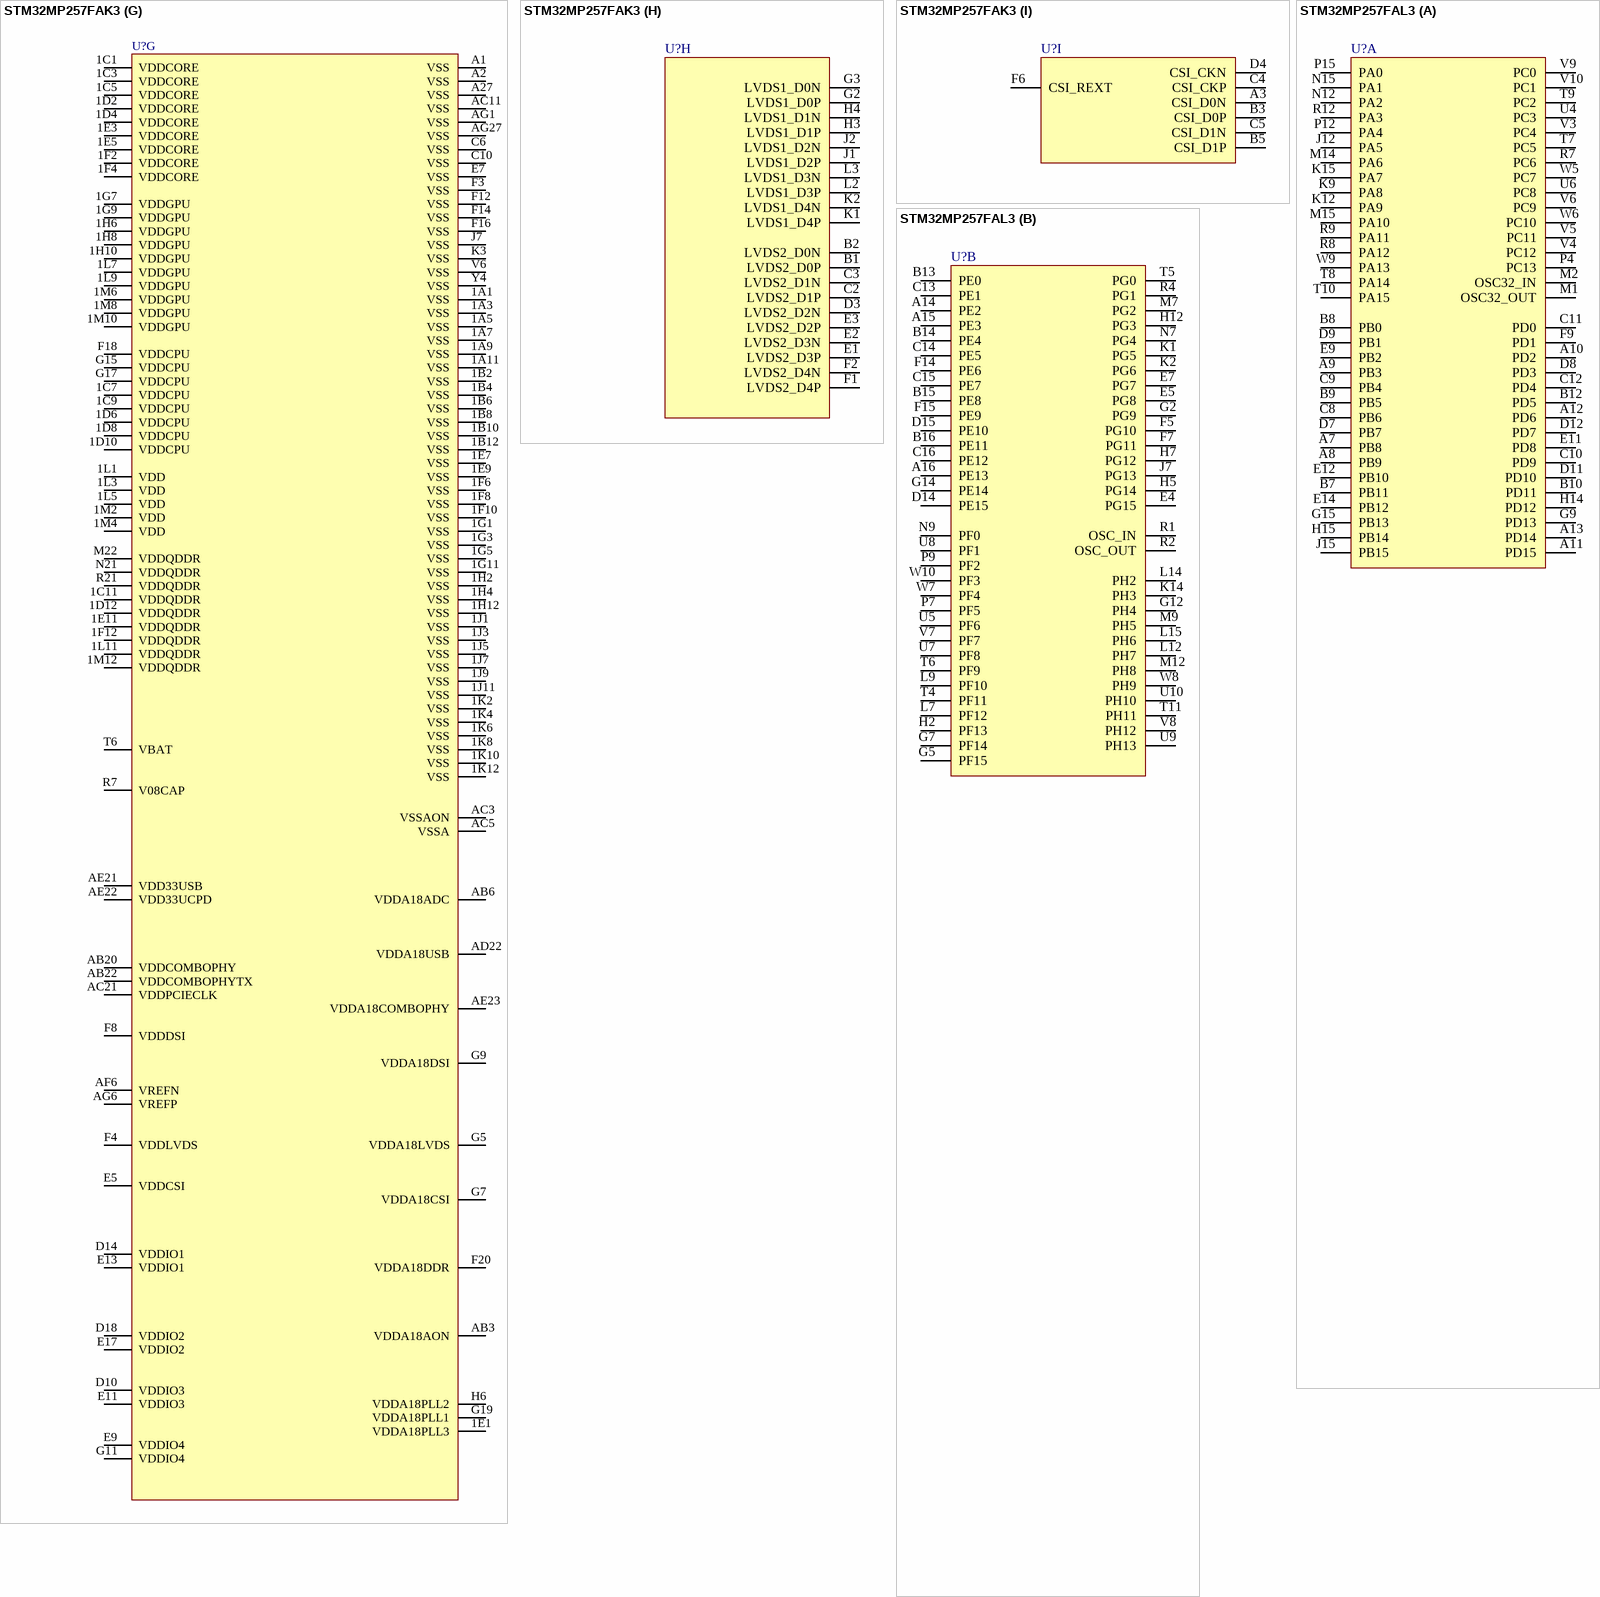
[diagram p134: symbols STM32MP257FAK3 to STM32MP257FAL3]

## STM32MP257FAK3
designator U?
part A pins: A11 PB11, A14 PB2, A15 PD11, A18 PD6, A19 PD1, A26 PB13, AA1 OSC32_OUT, AA2 OSC32_IN, AA9 PC3, AA17 PA8, AB10 PC6, AB12 PA14, AB14 PC0, AC9 PC4, AC13 PA12, AC19 PA1, AD8 PC11, AD10 PC5, AD12 PA11, AD14 PA13, AD18 PA3, AE6 PB15, AE7 PC12, AE9 PC9, AE12 PC2, AE13 PA15, AE15 PA10, AE17 PA5, AE18 PA7, AF5 PA0, AF9 PC7, AF15 PA9, AF17 PA2, AF18 PA6, AG9 PC8, AG10 PC10, AG14 PC1, AG17 PA4, B11 PB10, B13 PB0, B14 PB3, B15 PB4, B17 PD0, B18 PD5, B26 PD12, C11 PB7, C12 PB1, C13 PB6, C14 PB5, C15 PD9, C16 PD8, C17 PD10, C18 PD4, C26 PB12, C27 PB14, D8 PB8, D12 PD2, D20 PD7, D25 PD13, E15 PD15, E19 PD14, F10 PB9, G13 PD3, W7 PC13
part B pins: A22 PE6, A23 PE9, AA7 PG3, AA11 PF5, AA13 PH9, AA15 PF0, AB8 PF7, AB16 PH4, AC7 PF6, AC15 PF2, AC17 PH2, AD4 PG1, AD6 PG4, AD16 PH8, AE4 PF11, AE5 PF10, AE8 PF9, AE10 PF8, AE11 PF1, AE14 PH11, AE16 PH7, AE19 PH3, AF2 OSC_OUT, AF7 PG0, AF10 PF4, AF11 PF3, AF13 PH12, AF14 PH10, AF19 PH6, AG2 OSC_IN, AG5 PG2, AG13 PH13, AG18 PH5, B19 PE0, B21 PE4, B22 PE7, B23 PE11, B25 PE14, C19 PE1, C20 PE2, C21 PE3, C22 PE5, C23 PE8, C24 PE13, C25 PE12, D22 PE10, D24 PE15, K6 PG15, L5 PG8, M3 PG9, M4 PG10, N1 PG14, N2 PG11, N3 PG12, P1 PG13, P2 PF13, P3 PF14, P4 PF12, R2 PF15, R3 PG5, T3 PG6, U2 PG7
part C pins: AA3 BOOT1, AA5 JTCK_SWCLK, AB1 BOOT2, AB2 BOOT3, AB4 PWR_CPUON, AC2 JTDO_SWDO, AD3 PWR_ON, AE1 NRST, AE2 JTMS_SWDIO, AE3 JTDI, AF1 PWR_LP, AF3 NJTRST, B27 PI11, D16 PI10, J3 PI6, J5 PI7, K4 PI5, L7 PI0, M6 PI1, N5 PI2, N7 PI3, P6 PI4, R5 PZ5, T4 PZ0, U1 PI9, U3 PZ9, U5 PI8, U7 PZ1, V1 PZ8, V2 PZ7, V3 PZ4, V4 PZ6, W2 PDR_ON, W3 NRSTC1MS, W5 PZ2, Y3 BOOT0, Y6 PZ3
part D pins: A6 DSI_D3P, A7 DSI_D2N, A10 DSI_D1N, B6 DSI_D3N, B7 DSI_D2P, B9 DSI_D0P, B10 DSI_D1P, C7 DSI_CKP, C8 DSI_CKN, C9 DSI_D0N, D6 DSI_REXT
part E pins: AA19 UCPD1_CC2, AB18 UCPD1_CC1, AD20 DNC, AD24 COMBOPHY_TX1N, AE20 USBH_HS_TXRTUNE, AE24 COMBOPHY_TX1P, AE25 PCIE_CLKINP, AE26 PCIE_CLKINN, AF21 USBH_HS_DP, AF22 USB3DR_DP, AF23 USB3DR_TXRTUNE, AF25 COMBOPHY_RX1N, AF26 PCIE_CLKOUTP, AF27 COMBOPHY_REXT, AG21 USBH_HS_DM, AG22 USB3DR_DM, AG25 COMBOPHY_RX1P, AG26 PCIE_CLKOUTN
part F pins: AA21 DDR_A30, AA23 DDR_A27, AA25 DDR_DQS0P, AA26 DDR_DQS0N, AB24 DDR_A26, AB25 DDR_DQM0, AB26 DDR_DQ0, AB27 DDR_DQ2, AC23 DDR_A28, AC25 DDR_A7, AC26 DDR_DQ1, AC27 DDR_DQ3, AD25 DDR_A1, E21 DDR_RESETN, E23 DDR_A23, E25 DDR_DQ19, E26 DDR_DQ17, F22 DDR_A22, F24 DDR_DQ18, F25 DDR_DQ16, F26 DDR_DQS2N, F27 DDR_DQS2P, G21 DDR_VREF, G23 DDR_A18, G25 DDR_DQ23, G26 DDR_DQ22, G27 DDR_DQM2, H22 DDR_A21, H24 DDR_A17, H25 DDR_DQ21, J21 DDR_A20, J23 DDR_A16, J25 DDR_DQ20, J26 DDR_DQ24, K22 DDR_ZQ, K24 DDR_A13, K25 DDR_DQ25, K26 DDR_DQ26, K27 DDR_DQ27, L21 DDR_A19, L23 DDR_A12, L25 DDR_DQ28, L26 DDR_DQS3P, L27 DDR_DQS3N, M24 DDR_A14, M25 DDR_DQM3, N23 DDR_A15, N25 DDR_DQ29, N26 DDR_DQ30, P22 DDR_A3, P24 DDR_A11, P25 DDR_DQ31, P26 DDR_DQ11, P27 DDR_DQ10, R23 DDR_A10, R25 DDR_DQS1N, R26 DDR_DQ9, R27 DDR_DQ8, T22 DDR_A9, T24 DDR_A5, T25 DDR_DQS1P, U21 DDR_A0, U23 DDR_A4, U25 DDR_DQ15, U26 DDR_DQM1, V22 DDR_A8, V24 DDR_A2, V25 DDR_DQ14, V26 DDR_DQ12, V27 DDR_DQ13, W21 DDR_A25, W23 DDR_A31, W25 DDR_DQ4, W26 DDR_DQ6, W27 DDR_DQ5, Y22 DDR_A29, Y24 DDR_A6, Y25 DDR_DQ7
part G pins: 1A1 VSS, 1A3 VSS, 1A5 VSS, 1A7 VSS, 1A9 VSS, 1A11 VSS, 1B2 VSS, 1B4 VSS, 1B6 VSS, 1B8 VSS, 1B10 VSS, 1B12 VSS, 1C1 VDDCORE, 1C3 VDDCORE, 1C5 VDDCORE, 1C7 VDDCPU, 1C9 VDDCPU, 1C11 VDDQDDR, 1D2 VDDCORE, 1D4 VDDCORE, 1D6 VDDCPU, 1D8 VDDCPU, 1D10 VDDCPU, 1D12 VDDQDDR, 1E1 VDDA18PLL3, 1E3 VDDCORE, 1E5 VDDCORE, 1E7 VSS, 1E9 VSS, 1E11 VDDQDDR, 1F2 VDDCORE, 1F4 VDDCORE, 1F6 VSS, 1F8 VSS, 1F10 VSS, 1F12 VDDQDDR, 1G1 VSS, 1G3 VSS, 1G5 VSS, 1G7 VDDGPU, 1G9 VDDGPU, 1G11 VSS, 1H2 VSS, 1H4 VSS, 1H6 VDDGPU, 1H8 VDDGPU, 1H10 VDDGPU, 1H12 VSS, 1J1 VSS, 1J3 VSS, 1J5 VSS, 1J7 VSS, 1J9 VSS, 1J11 VSS, 1K2 VSS, 1K4 VSS, 1K6 VSS, 1K8 VSS, 1K10 VSS, 1K12 VSS, 1L1 VDD, 1L3 VDD, 1L5 VDD, 1L7 VDDGPU, 1L9 VDDGPU, 1L11 VDDQDDR, 1M2 VDD, 1M4 VDD, 1M6 VDDGPU, 1M8 VDDGPU, 1M10 VDDGPU, 1M12 VDDQDDR, A1 VSS, A2 VSS, A27 VSS, AB3 VDDA18AON, AB6 VDDA18ADC, AB20 VDDCOMBOPHY, AB22 VDDCOMBOPHYTX, AC3 VSSAON, AC5 VSSA, AC11 VSS, AC21 VDDPCIECLK, AD22 VDDA18USB, AE21 VDD33USB, AE22 VDD33UCPD, AE23 VDDA18COMBOPHY, AF6 VREFN, AG1 VSS, AG6 VREFP, AG27 VSS, C6 VSS, C10 VSS, D10 VDDIO3, D14 VDDIO1, D18 VDDIO2, E5 VDDCSI, E7 VSS, E9 VDDIO4, E11 VDDIO3, E13 VDDIO1, E17 VDDIO2, F3 VSS, F4 VDDLVDS, F8 VDDDSI, F12 VSS, F14 VSS, F16 VSS, F18 VDDCPU, F20 VDDA18DDR, G5 VDDA18LVDS, G7 VDDA18CSI, G9 VDDA18DSI, G11 VDDIO4, G15 VDDCPU, G17 VDDCPU, G19 VDDA18PLL1, H6 VDDA18PLL2, J7 VSS, K3 VSS, M22 VDDQDDR, N21 VDDQDDR, R7 V08CAP, R21 VDDQDDR, T6 VBAT, V6 VSS, Y4 VSS
part H pins: B1 LVDS2_D0P, B2 LVDS2_D0N, C2 LVDS2_D1P, C3 LVDS2_D1N, D3 LVDS2_D2N, E1 LVDS2_D3P, E2 LVDS2_D3N, E3 LVDS2_D2P, F1 LVDS2_D4P, F2 LVDS2_D4N, G2 LVDS1_D0P, G3 LVDS1_D0N, H3 LVDS1_D1P, H4 LVDS1_D1N, J1 LVDS1_D2P, J2 LVDS1_D2N, K1 LVDS1_D4P, K2 LVDS1_D4N, L2 LVDS1_D3P, L3 LVDS1_D3N
part I pins: A3 CSI_D0N, B3 CSI_D0P, B5 CSI_D1P, C4 CSI_CKP, C5 CSI_D1N, D4 CSI_CKN, F6 CSI_REXT

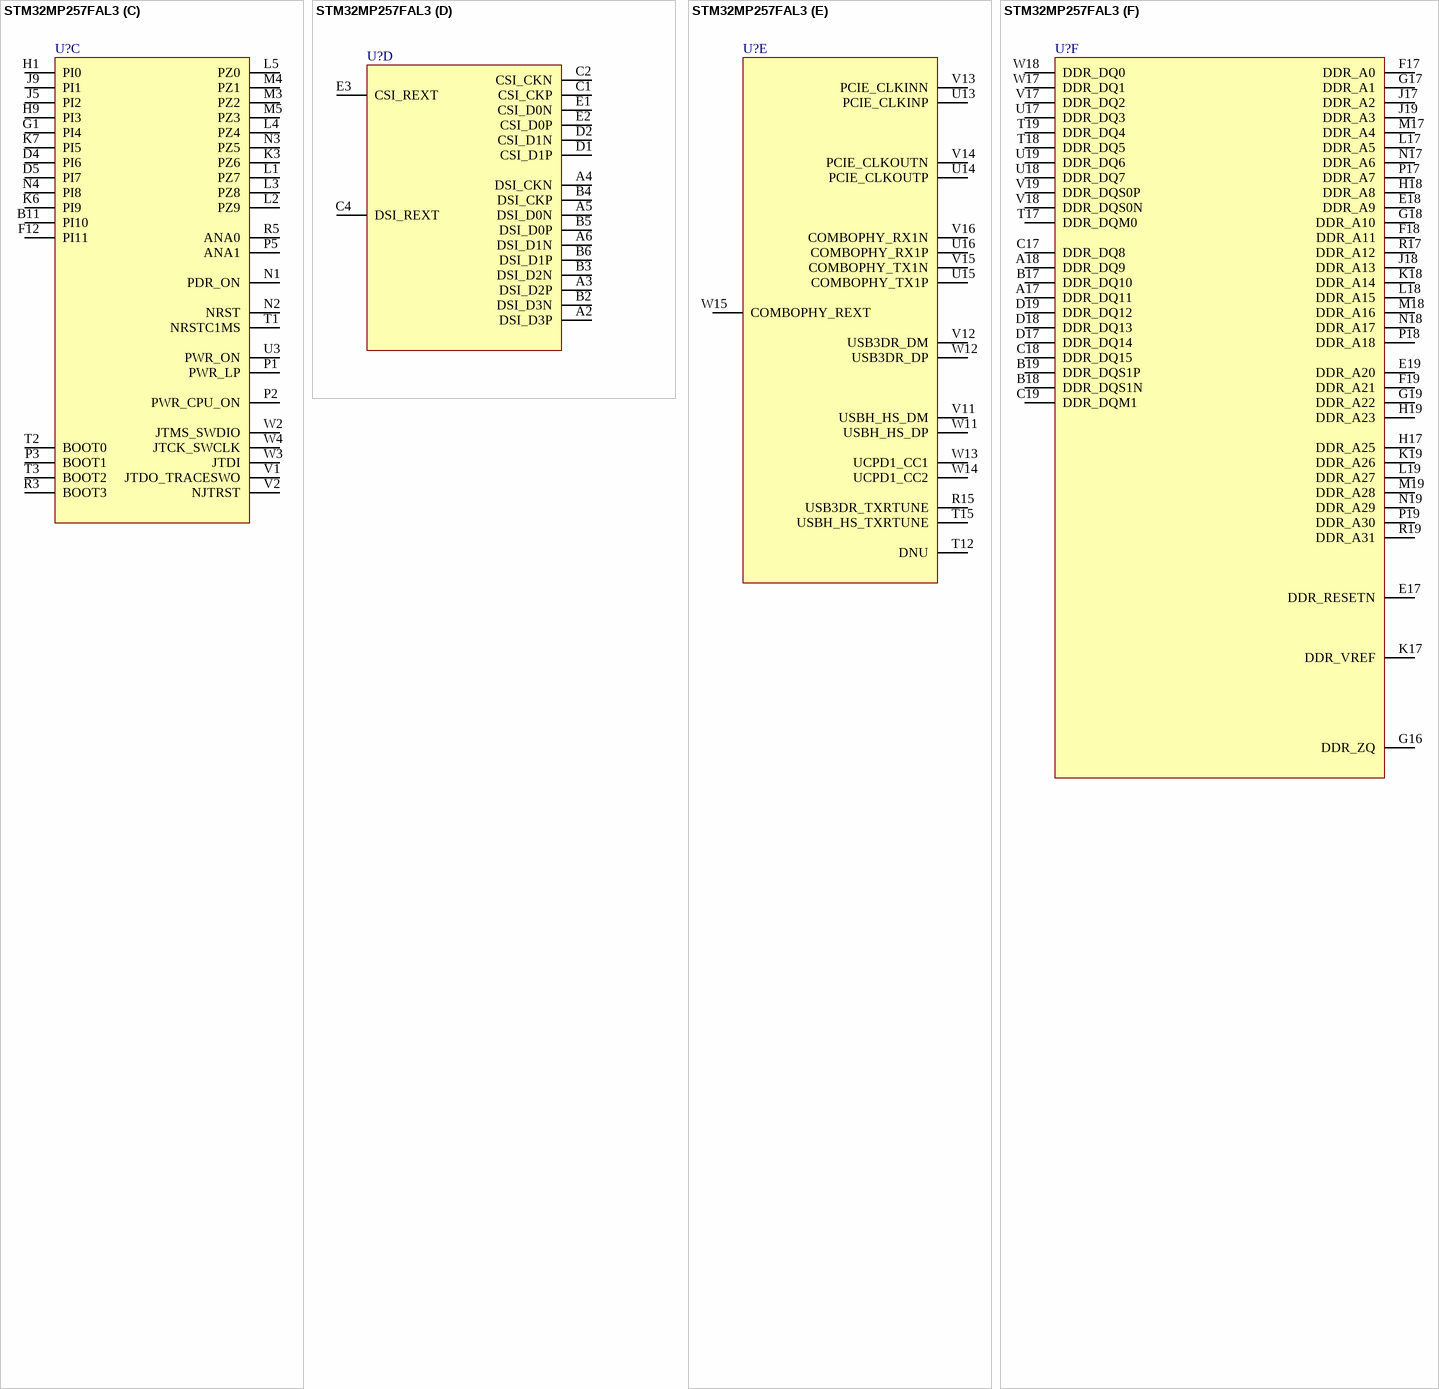
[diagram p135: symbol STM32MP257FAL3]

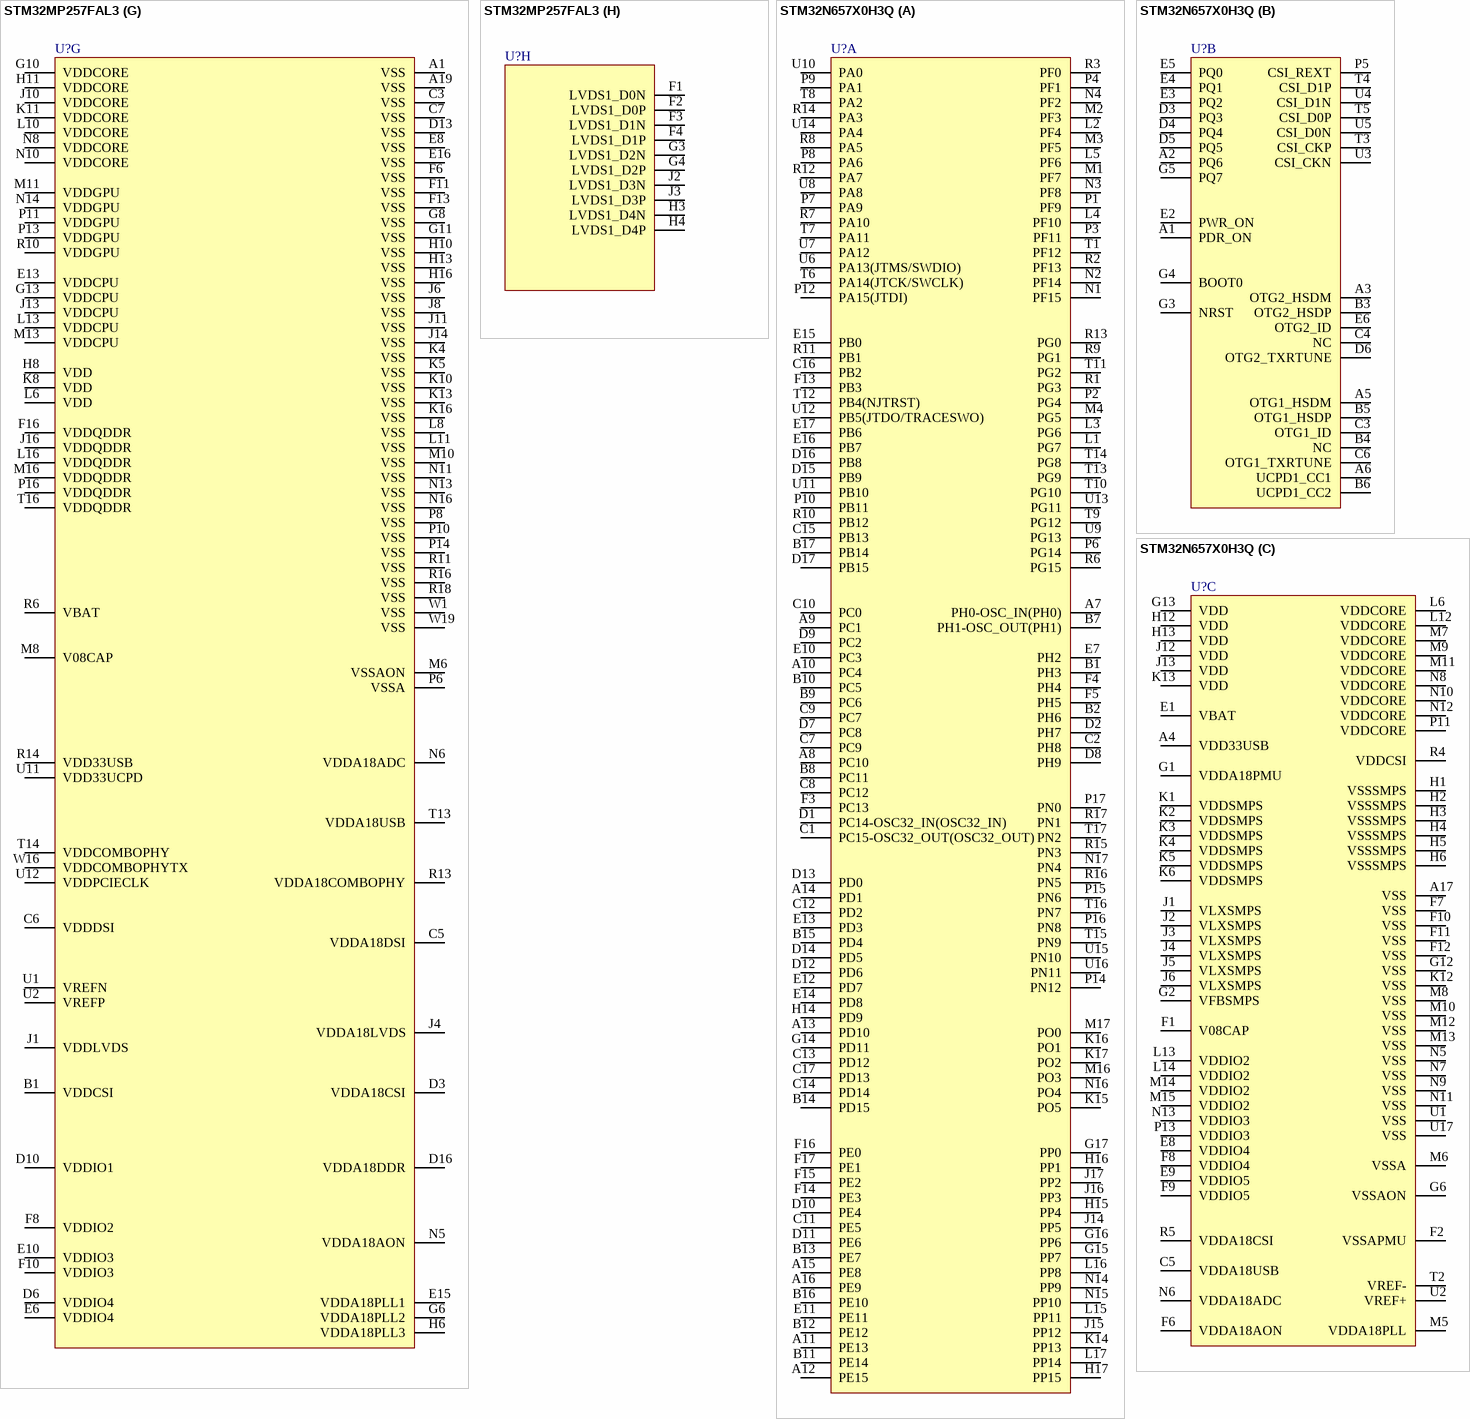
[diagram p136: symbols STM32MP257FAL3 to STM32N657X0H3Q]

## STM32MP257FAL3
designator U?
part A pins: A7 PB8, A8 PB9, A9 PB3, A10 PD2, A11 PD15, A12 PD6, A13 PD14, B7 PB11, B8 PB0, B9 PB5, B10 PD11, B12 PD5, C8 PB6, C9 PB4, C10 PD9, C11 PD0, C12 PD4, D7 PB7, D8 PD3, D9 PB1, D11 PD10, D12 PD7, E9 PB2, E11 PD8, E12 PB10, E14 PB12, F9 PD1, G9 PD13, G15 PB13, H14 PD12, H15 PB14, J12 PA5, J15 PB15, K9 PA8, K12 PA9, K15 PA7, M1 OSC32_OUT, M2 OSC32_IN, M14 PA6, M15 PA10, N12 PA2, N15 PA1, P4 PC13, P12 PA4, P15 PA0, R7 PC6, R8 PA12, R9 PA11, R12 PA3, T7 PC5, T8 PA14, T9 PC2, T10 PA15, U4 PC3, U6 PC8, V3 PC4, V4 PC12, V5 PC11, V6 PC9, V9 PC0, V10 PC1, W5 PC7, W6 PC10, W9 PA13
part B pins: A14 PE2, A15 PE3, A16 PE13, B13 PE0, B14 PE4, B15 PE8, B16 PE11, C13 PE1, C14 PE5, C15 PE7, C16 PE12, D14 PE15, D15 PE10, E4 PG15, E5 PG8, E7 PG7, F5 PG10, F7 PG11, F14 PE6, F15 PE9, G2 PG9, G5 PF15, G7 PF14, G12 PH4, G14 PE14, H2 PF13, H5 PG14, H7 PG12, H12 PG3, J7 PG13, K1 PG5, K2 PG6, K14 PH3, L7 PF12, L9 PF10, L12 PH7, L14 PH2, L15 PH6, M7 PG2, M9 PH5, M12 PH8, N7 PG4, N9 PF0, P7 PF5, P9 PF2, R1 OSC_IN, R2 OSC_OUT, R4 PG1, T4 PF11, T5 PG0, T6 PF9, T11 PH11, U5 PF6, U7 PF8, U8 PF1, U9 PH13, U10 PH10, V7 PF7, V8 PH12, W7 PF4, W8 PH9, W10 PF3
part C pins: B11 PI10, D4 PI6, D5 PI7, F12 PI11, G1 PI4, H1 PI0, H9 PI3, J5 PI2, J9 PI1, K3 PZ6, K6 PI9, K7 PI5, L1 PZ7, L2 PZ9, L3 PZ8, L4 PZ4, L5 PZ0, M3 PZ2, M4 PZ1, M5 PZ3, N1 PDR_ON, N2 NRST, N3 PZ5, N4 PI8, P1 PWR_LP, P2 PWR_CPU_ON, P3 BOOT1, P5 ANA1, R3 BOOT3, R5 ANA0, T1 NRSTC1MS, T2 BOOT0, T3 BOOT2, U3 PWR_ON, V1 JTDO_TRACESWO, V2 NJTRST, W2 JTMS_SWDIO, W3 JTDI, W4 JTCK_SWCLK
part D pins: A2 DSI_D3P, A3 DSI_D2P, A4 DSI_CKN, A5 DSI_D0N, A6 DSI_D1N, B2 DSI_D3N, B3 DSI_D2N, B4 DSI_CKP, B5 DSI_D0P, B6 DSI_D1P, C1 CSI_CKP, C2 CSI_CKN, C4 DSI_REXT, D1 CSI_D1P, D2 CSI_D1N, E1 CSI_D0N, E2 CSI_D0P, E3 CSI_REXT
part E pins: R15 USB3DR_TXRTUNE, T12 DNU, T15 USBH_HS_TXRTUNE, U13 PCIE_CLKINP, U14 PCIE_CLKOUTP, U15 COMBOPHY_TX1P, U16 COMBOPHY_RX1P, V11 USBH_HS_DM, V12 USB3DR_DM, V13 PCIE_CLKINN, V14 PCIE_CLKOUTN, V15 COMBOPHY_TX1N, V16 COMBOPHY_RX1N, W11 USBH_HS_DP, W12 USB3DR_DP, W13 UCPD1_CC1, W14 UCPD1_CC2, W15 COMBOPHY_REXT
part F pins: A17 DDR_DQ11, A18 DDR_DQ9, B17 DDR_DQ10, B18 DDR_DQS1N, B19 DDR_DQS1P, C17 DDR_DQ8, C18 DDR_DQ15, C19 DDR_DQM1, D17 DDR_DQ14, D18 DDR_DQ13, D19 DDR_DQ12, E17 DDR_RESETN, E18 DDR_A9, E19 DDR_A20, F17 DDR_A0, F18 DDR_A11, F19 DDR_A21, G16 DDR_ZQ, G17 DDR_A1, G18 DDR_A10, G19 DDR_A22, H17 DDR_A25, H18 DDR_A8, H19 DDR_A23, J17 DDR_A2, J18 DDR_A13, J19 DDR_A3, K17 DDR_VREF, K18 DDR_A14, K19 DDR_A26, L17 DDR_A5, L18 DDR_A15, L19 DDR_A27, M17 DDR_A4, M18 DDR_A16, M19 DDR_A28, N17 DDR_A6, N18 DDR_A17, N19 DDR_A29, P17 DDR_A7, P18 DDR_A18, P19 DDR_A30, R17 DDR_A12, R19 DDR_A31, T17 DDR_DQM0, T18 DDR_DQ5, T19 DDR_DQ4, U17 DDR_DQ3, U18 DDR_DQ7, U19 DDR_DQ6, V17 DDR_DQ2, V18 DDR_DQS0N, V19 DDR_DQS0P, W17 DDR_DQ1, W18 DDR_DQ0
part G pins: A1 VSS, A19 VSS, B1 VDDCSI, C3 VSS, C5 VDDA18DSI, C6 VDDDSI, C7 VSS, D3 VDDA18CSI, D6 VDDIO4, D10 VDDIO1, D13 VSS, D16 VDDA18DDR, E6 VDDIO4, E8 VSS, E10 VDDIO3, E13 VDDCPU, E15 VDDA18PLL1, E16 VSS, F6 VSS, F8 VDDIO2, F10 VDDIO3, F11 VSS, F13 VSS, F16 VDDQDDR, G6 VDDA18PLL2, G8 VSS, G10 VDDCORE, G11 VSS, G13 VDDCPU, H6 VDDA18PLL3, H8 VDD, H10 VSS, H11 VDDCORE, H13 VSS, H16 VSS, J1 VDDLVDS, J4 VDDA18LVDS, J6 VSS, J8 VSS, J10 VDDCORE, J11 VSS, J13 VDDCPU, J14 VSS, J16 VDDQDDR, K4 VSS, K5 VSS, K8 VDD, K10 VSS, K11 VDDCORE, K13 VSS, K16 VSS, L6 VDD, L8 VSS, L10 VDDCORE, L11 VSS, L13 VDDCPU, L16 VDDQDDR, M6 VSSAON, M8 V08CAP, M10 VSS, M11 VDDGPU, M13 VDDCPU, M16 VDDQDDR, N5 VDDA18AON, N6 VDDA18ADC, N8 VDDCORE, N10 VDDCORE, N11 VSS, N13 VSS, N14 VDDGPU, N16 VSS, P6 VSSA, P8 VSS, P10 VSS, P11 VDDGPU, P13 VDDGPU, P14 VSS, P16 VDDQDDR, R6 VBAT, R10 VDDGPU, R11 VSS, R13 VDDA18COMBOPHY, R14 VDD33USB, R16 VSS, R18 VSS, T13 VDDA18USB, T14 VDDCOMBOPHY, T16 VDDQDDR, U1 VREFN, U2 VREFP, U11 VDD33UCPD, U12 VDDPCIECLK, W1 VSS, W16 VDDCOMBOPHYTX, W19 VSS
part H pins: F1 LVDS1_D0N, F2 LVDS1_D0P, F3 LVDS1_D1N, F4 LVDS1_D1P, G3 LVDS1_D2N, G4 LVDS1_D2P, H3 LVDS1_D4N, H4 LVDS1_D4P, J2 LVDS1_D3N, J3 LVDS1_D3P

## STM32N657X0H3Q
designator U?
part A pins: A7 PH0-OSC_IN(PH0), A8 PC10, A9 PC1, A10 PC4, A11 PE13, A12 PE15, A13 PD10, A14 PD1, A15 PE8, A16 PE9, B1 PH3, B2 PH6, B7 PH1-OSC_OUT(PH1), B8 PC11, B9 PC6, B10 PC5, B11 PE14, B12 PE12, B13 PE7, B14 PD15, B15 PD4, B16 PE10, B17 PB14, C1 PC15-OSC32_OUT(OSC32_OUT), C2 PH8, C7 PC9, C8 PC12, C9 PC7, C10 PC0, C11 PE5, C12 PD2, C13 PD12, C14 PD14, C15 PB13, C16 PB2, C17 PD13, D1 PC14-OSC32_IN(OSC32_IN), D2 PH7, D7 PC8, D8 PH9, D9 PC2, D10 PE4, D11 PE6, D12 PD6, D13 PD0, D14 PD5, D15 PB9, D16 PB8, D17 PB15, E7 PH2, E10 PC3, E11 PE11, E12 PD7, E13 PD3, E14 PD8, E15 PB0, E16 PB7, E17 PB6, F3 PC13, F4 PH4, F5 PH5, F13 PB3, F14 PE3, F15 PE2, F16 PE0, F17 PE1, G14 PD11, G15 PP7, G16 PP6, G17 PP0, H14 PD9, H15 PP4, H16 PP1, H17 PP15, J14 PP5, J15 PP12, J16 PP3, J17 PP2, K14 PP13, K15 PO5, K16 PO1, K17 PO2, L1 PG7, L2 PF4, L3 PG6, L4 PF10, L5 PF6, L15 PP11, L16 PP8, L17 PP14, M1 PF7, M2 PF3, M3 PF5, M4 PG5, M16 PO3, M17 PO0, N1 PF15, N2 PF14, N3 PF8, N4 PF2, N14 PP9, N15 PP10, N16 PO4, N17 PN4, P1 PF9, P2 PG4, P3 PF11, P4 PF1, P6 PG14, P7 PA9, P8 PA6, P9 PA1, P10 PB11, P12 PA15(JTDI), P14 PN12, P15 PN6, P16 PN8, P17 PN0, R1 PG3, R2 PF13, R3 PF0, R6 PG15, R7 PA10, R8 PA5, R9 PG1, R10 PB12, R11 PB1, R12 PA7, R13 PG0, R14 PA3, R15 PN3, R16 PN5, R17 PN1, T1 PF12, T6 PA14(JTCK/SWCLK) , T7 PA11, T8 PA2, T9 PG12, T10 PG10, T11 PG2, T12 PB4(NJTRST), T13 PG9, T14 PG8, T15 PN9, T16 PN7, T17 PN2, U6 PA13(JTMS/SWDIO), U7 PA12, U8 PA8, U9 PG13, U10 PA0, U11 PB10, U12 PB5(JTDO/TRACESWO), U13 PG11, U14 PA4, U15 PN10, U16 PN11
part B pins: A1 PDR_ON, A2 PQ6, A3 OTG2_HSDM, A5 OTG1_HSDM, A6 UCPD1_CC1, B3 OTG2_HSDP, B4 NC, B5 OTG1_HSDP, B6 UCPD1_CC2, C3 OTG1_ID, C4 NC, C6 OTG1_TXRTUNE, D3 PQ3, D4 PQ4, D5 PQ5, D6 OTG2_TXRTUNE, E2 PWR_ON, E3 PQ2, E4 PQ1, E5 PQ0, E6 OTG2_ID, G3 NRST, G4 BOOT0, G5 PQ7, P5 CSI_REXT, T3 CSI_CKP, T4 CSI_D1P, T5 CSI_D0P, U3 CSI_CKN, U4 CSI_D1N, U5 CSI_D0N
part C pins: A4 VDD33USB, A17 VSS, C5 VDDA18USB, E1 VBAT, E8 VDDIO4, E9 VDDIO5, F1 V08CAP, F2 VSSAPMU, F6 VDDA18AON, F7 VSS, F8 VDDIO4, F9 VDDIO5, F10 VSS, F11 VSS, F12 VSS, G1 VDDA18PMU, G2 VFBSMPS, G6 VSSAON, G12 VSS, G13 VDD, H1 VSSSMPS, H2 VSSSMPS, H3 VSSSMPS, H4 VSSSMPS, H5 VSSSMPS, H6 VSSSMPS, H12 VDD, H13 VDD, J1 VLXSMPS, J2 VLXSMPS, J3 VLXSMPS, J4 VLXSMPS, J5 VLXSMPS, J6 VLXSMPS, J12 VDD, J13 VDD, K1 VDDSMPS, K2 VDDSMPS, K3 VDDSMPS, K4 VDDSMPS, K5 VDDSMPS, K6 VDDSMPS, K12 VSS, K13 VDD, L6 VDDCORE, L12 VDDCORE, L13 VDDIO2, L14 VDDIO2, M5 VDDA18PLL, M6 VSSA, M7 VDDCORE, M8 VSS, M9 VDDCORE, M10 VSS, M11 VDDCORE, M12 VSS, M13 VSS, M14 VDDIO2, M15 VDDIO2, N5 VSS, N6 VDDA18ADC, N7 VSS, N8 VDDCORE, N9 VSS, N10 VDDCORE, N11 VSS, N12 VDDCORE, N13 VDDIO3, P11 VDDCORE, P13 VDDIO3, R4 VDDCSI, R5 VDDA18CSI, T2 VREF-, U1 VSS, U2 VREF+, U17 VSS

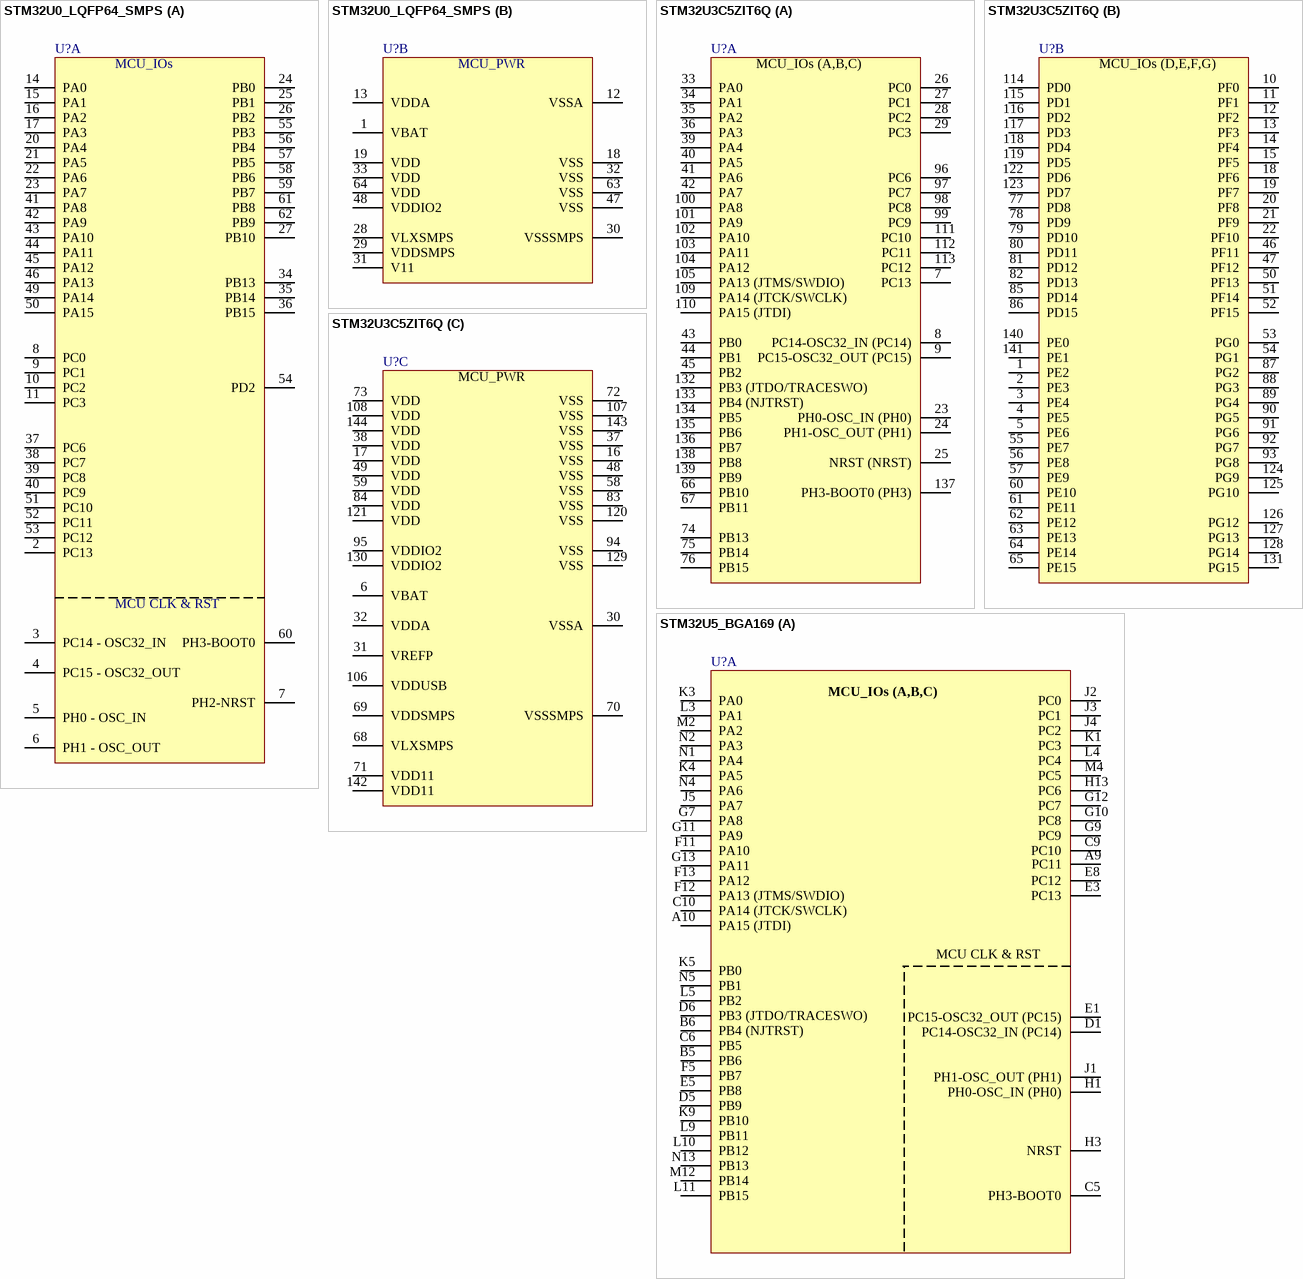
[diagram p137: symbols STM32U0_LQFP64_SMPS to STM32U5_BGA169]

## STM32U0_LQFP64_SMPS
designator U?
part A pins: 2 PC13, 3 PC14 - OSC32_IN, 4 PC15 - OSC32_OUT, 5 PH0 - OSC_IN, 6 PH1 - OSC_OUT, 7 PH2-NRST, 8 PC0, 9 PC1, 10 PC2, 11 PC3, 14 PA0, 15 PA1, 16 PA2, 17 PA3, 20 PA4, 21 PA5, 22 PA6, 23 PA7, 24 PB0, 25 PB1, 26 PB2, 27 PB10, 34 PB13, 35 PB14, 36 PB15, 37 PC6, 38 PC7, 39 PC8, 40 PC9, 41 PA8, 42 PA9, 43 PA10 (hiz), 44 PA11, 45 PA12, 46 PA13, 49 PA14, 50 PA15, 51 PC10, 52 PC11, 53 PC12, 54 PD2, 55 PB3, 56 PB4, 57 PB5, 58 PB6, 59 PB7, 60 PH3-BOOT0, 61 PB8, 62 PB9
part B pins: 1 VBAT, 12 VSSA, 13 VDDA, 18 VSS, 19 VDD, 28 VLXSMPS, 29 VDDSMPS, 30 VSSSMPS, 31 V11, 32 VSS, 33 VDD, 47 VSS, 48 VDDIO2, 63 VSS, 64 VDD

## STM32U3C5ZIT6Q
designator U?
part A pins: 7 PC13, 8 PC14-OSC32_IN (PC14), 9 PC15-OSC32_OUT (PC15), 23 PH0-OSC_IN (PH0), 24 PH1-OSC_OUT (PH1), 25 NRST (NRST), 26 PC0, 27 PC1, 28 PC2, 29 PC3, 33 PA0, 34 PA1, 35 PA2, 36 PA3, 39 PA4, 40 PA5, 41 PA6, 42 PA7, 43 PB0, 44 PB1, 45 PB2, 66 PB10, 67 PB11, 74 PB13, 75 PB14, 76 PB15, 96 PC6, 97 PC7, 98 PC8, 99 PC9, 100 PA8, 101 PA9, 102 PA10, 103 PA11, 104 PA12, 105 PA13 (JTMS/SWDIO), 109 PA14 (JTCK/SWCLK), 110 PA15 (JTDI), 111 PC10, 112 PC11, 113 PC12, 132 PB3 (JTDO/TRACESWO), 133 PB4 (NJTRST), 134 PB5, 135 PB6, 136 PB7, 137 PH3-BOOT0 (PH3), 138 PB8, 139 PB9
part B pins: 1 PE2, 2 PE3, 3 PE4, 4 PE5, 5 PE6, 10 PF0, 11 PF1, 12 PF2, 13 PF3, 14 PF4, 15 PF5, 18 PF6, 19 PF7, 20 PF8, 21 PF9, 22 PF10, 46 PF11, 47 PF12, 50 PF13, 51 PF14, 52 PF15, 53 PG0, 54 PG1, 55 PE7, 56 PE8, 57 PE9, 60 PE10, 61 PE11, 62 PE12, 63 PE13, 64 PE14, 65 PE15, 77 PD8, 78 PD9, 79 PD10, 80 PD11, 81 PD12, 82 PD13, 85 PD14, 86 PD15, 87 PG2, 88 PG3, 89 PG4, 90 PG5, 91 PG6, 92 PG7, 93 PG8, 114 PD0, 115 PD1, 116 PD2, 117 PD3, 118 PD4, 119 PD5, 122 PD6, 123 PD7, 124 PG9, 125 PG10, 126 PG12, 127 PG13, 128 PG14, 131 PG15, 140 PE0, 141 PE1
part C pins: 6 VBAT, 16 VSS, 17 VDD, 30 VSSA, 31 VREFP, 32 VDDA, 37 VSS, 38 VDD, 48 VSS, 49 VDD, 58 VSS, 59 VDD, 68 VLXSMPS, 69 VDDSMPS, 70 VSSSMPS, 71 VDD11, 72 VSS, 73 VDD, 83 VSS, 84 VDD, 94 VSS, 95 VDDIO2, 106 VDDUSB, 107 VSS, 108 VDD, 120 VSS, 121 VDD, 129 VSS, 130 VDDIO2, 142 VDD11, 143 VSS, 144 VDD

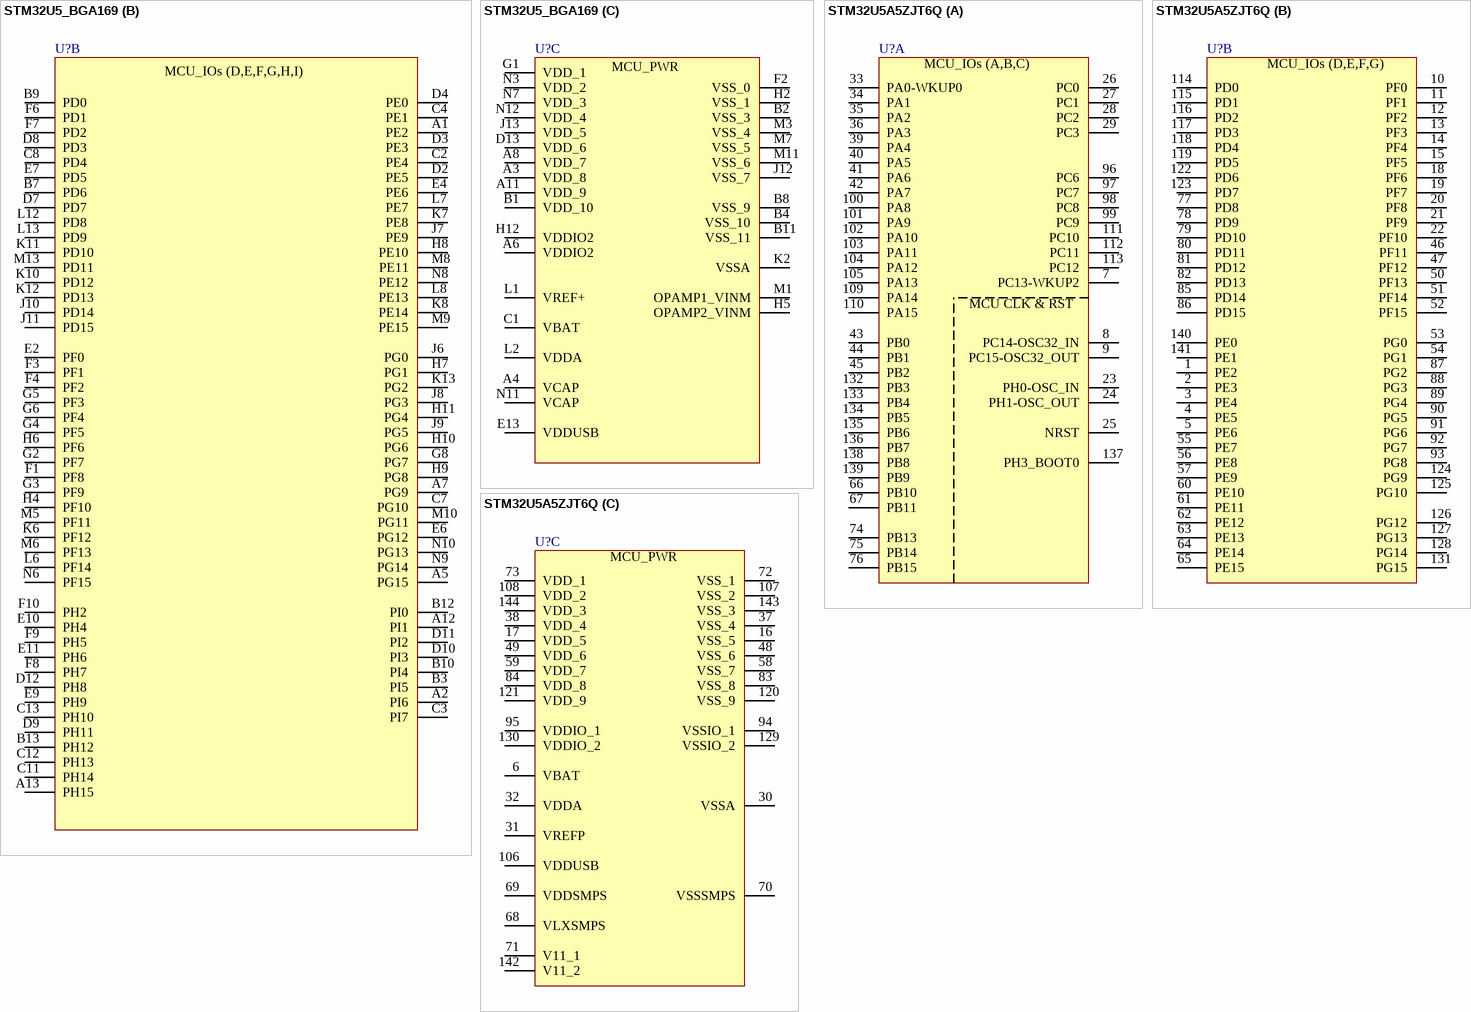
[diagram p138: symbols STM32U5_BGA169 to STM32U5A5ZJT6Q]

## STM32U5_BGA169
designator U?
part A pins: A9 PC11, A10 PA15 (JTDI), B5 PB6, B6 PB4 (NJTRST), C5 PH3-BOOT0, C6 PB5, C9 PC10, C10 PA14 (JTCK/SWCLK), D1 PC14-OSC32_IN (PC14), D5 PB9, D6 PB3 (JTDO/TRACESWO), E1 PC15-OSC32_OUT (PC15), E3 PC13, E5 PB8, E8 PC12, F5 PB7, F11 PA10, F12 PA13 (JTMS/SWDIO), F13 PA12, G7 PA8, G9 PC9, G10 PC8, G11 PA9, G12 PC7, G13 PA11, H1 PH0-OSC_IN (PH0), H3 NRST, H13 PC6, J1 PH1-OSC_OUT (PH1), J2 PC0, J3 PC1, J4 PC2, J5 PA7, K1 PC3, K3 PA0, K4 PA5, K5 PB0, K9 PB10, L3 PA1, L4 PC4, L5 PB2, L9 PB11, L10 PB12, L11 PB15, M2 PA2, M4 PC5, M12 PB14, N1 PA4, N2 PA3, N4 PA6, N5 PB1, N13 PB13
part B pins: A1 PE2, A2 PI6, A5 PG15, A7 PG9, A12 PI1, A13 PH15, B3 PI5, B7 PD6, B9 PD0, B10 PI4, B12 PI0, B13 PH12, C2 PE4, C3 PI7, C4 PE1, C7 PG10, C8 PD4, C11 PH14, C12 PH13, C13 PH10, D2 PE5, D3 PE3, D4 PE0, D7 PD7, D8 PD3, D9 PH11, D10 PI3, D11 PI2, D12 PH8, E2 PF0, E4 PE6, E6 PG12, E7 PD5, E9 PH9, E10 PH4, E11 PH6, F1 PF8, F3 PF1, F4 PF2, F6 PD1, F7 PD2, F8 PH7, F9 PH5, F10 PH2, G2 PF7, G3 PF9, G4 PF5, G5 PF3, G6 PF4, G8 PG7, H4 PF10, H6 PF6, H7 PG1, H8 PE10, H9 PG8, H10 PG6, H11 PG4, J6 PG0, J7 PE9, J8 PG3, J9 PG5, J10 PD14, J11 PD15, K6 PF12, K7 PE8, K8 PE14, K10 PD12, K11 PD10, K12 PD13, K13 PG2, L6 PF14, L7 PE7, L8 PE13, L12 PD8, L13 PD9, M5 PF11, M6 PF13, M8 PE11, M9 PE15, M10 PG11, M13 PD11, N6 PF15, N8 PE12, N9 PG14, N10 PG13
part C pins: A3 VDD_8, A4 VCAP, A6 VDDIO2, A8 VDD_7, A11 VDD_9, B1 VDD_10, B2 VSS_3, B4 VSS_10, B8 VSS_9, B11 VSS_11, C1 VBAT, D13 VDD_6, E13 VDDUSB, F2 VSS_0, G1 VDD_1, H2 VSS_1, H5 OPAMP2_VINM, H12 VDDIO2, J12 VSS_7, J13 VDD_5, K2 VSSA, L1 VREF+, L2 VDDA, M1 OPAMP1_VINM, M3 VSS_4, M7 VSS_5, M11 VSS_6, N3 VDD_2, N7 VDD_3, N11 VCAP, N12 VDD_4

## STM32U5A5ZJT6Q
designator U?
part A pins: 7 PC13-WKUP2, 8 PC14-OSC32_IN, 9 PC15-OSC32_OUT, 23 PH0-OSC_IN, 24 PH1-OSC_OUT, 25 NRST, 26 PC0, 27 PC1, 28 PC2, 29 PC3, 33 PA0-WKUP0, 34 PA1, 35 PA2, 36 PA3, 39 PA4, 40 PA5, 41 PA6, 42 PA7, 43 PB0, 44 PB1, 45 PB2, 66 PB10, 67 PB11, 74 PB13, 75 PB14, 76 PB15, 96 PC6, 97 PC7, 98 PC8, 99 PC9, 100 PA8, 101 PA9, 102 PA10, 103 PA11, 104 PA12, 105 PA13, 109 PA14, 110 PA15, 111 PC10, 112 PC11, 113 PC12, 132 PB3, 133 PB4, 134 PB5, 135 PB6, 136 PB7, 137 PH3_BOOT0, 138 PB8, 139 PB9
part B pins: 1 PE2, 2 PE3, 3 PE4, 4 PE5, 5 PE6, 10 PF0, 11 PF1, 12 PF2, 13 PF3, 14 PF4, 15 PF5, 18 PF6, 19 PF7, 20 PF8, 21 PF9, 22 PF10, 46 PF11, 47 PF12, 50 PF13, 51 PF14, 52 PF15, 53 PG0, 54 PG1, 55 PE7, 56 PE8, 57 PE9, 60 PE10, 61 PE11, 62 PE12, 63 PE13, 64 PE14, 65 PE15, 77 PD8, 78 PD9, 79 PD10, 80 PD11, 81 PD12, 82 PD13, 85 PD14, 86 PD15, 87 PG2, 88 PG3, 89 PG4, 90 PG5, 91 PG6, 92 PG7, 93 PG8, 114 PD0, 115 PD1, 116 PD2, 117 PD3, 118 PD4, 119 PD5, 122 PD6, 123 PD7, 124 PG9, 125 PG10, 126 PG12, 127 PG13, 128 PG14, 131 PG15, 140 PE0, 141 PE1
part C pins: 6 VBAT, 16 VSS_5, 17 VDD_5, 30 VSSA, 31 VREFP, 32 VDDA, 37 VSS_4, 38 VDD_4, 48 VSS_6, 49 VDD_6, 58 VSS_7, 59 VDD_7, 68 VLXSMPS, 69 VDDSMPS, 70 VSSSMPS, 71 V11_1, 72 VSS_1, 73 VDD_1, 83 VSS_8, 84 VDD_8, 94 VSSIO_1, 95 VDDIO_1, 106 VDDUSB, 107 VSS_2, 108 VDD_2, 120 VSS_9, 121 VDD_9, 129 VSSIO_2, 130 VDDIO_2, 142 V11_2, 143 VSS_3, 144 VDD_3

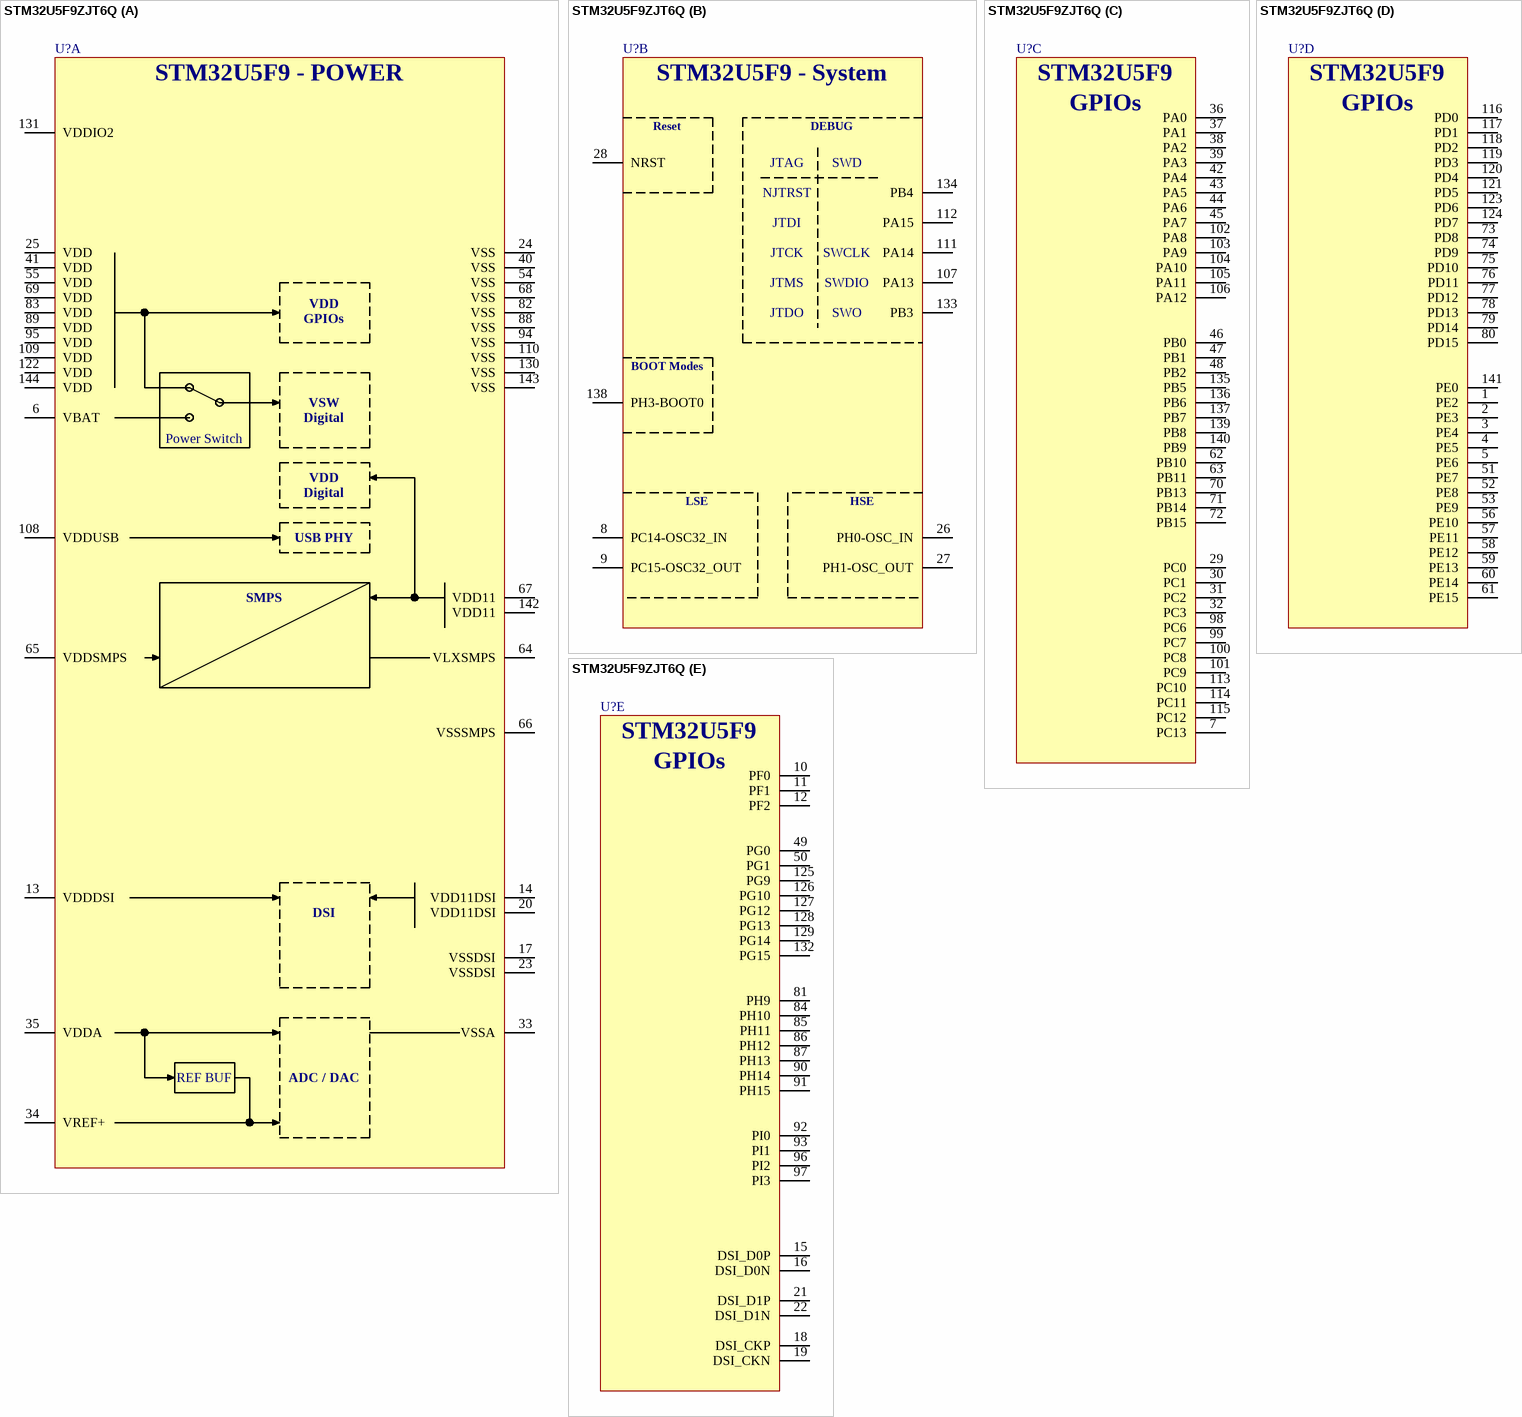
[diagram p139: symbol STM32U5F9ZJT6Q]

## STM32U5F9ZJT6Q
designator U?
part A pins: 6 VBAT, 13 VDDDSI, 14 VDD11DSI, 17 VSSDSI, 20 VDD11DSI, 23 VSSDSI, 24 VSS, 25 VDD, 33 VSSA, 34 VREF+, 35 VDDA, 40 VSS, 41 VDD, 54 VSS, 55 VDD, 64 VLXSMPS, 65 VDDSMPS, 66 VSSSMPS, 67 VDD11, 68 VSS, 69 VDD, 82 VSS, 83 VDD, 88 VSS, 89 VDD, 94 VSS, 95 VDD, 108 VDDUSB, 109 VDD, 110 VSS, 122 VDD, 130 VSS, 131 VDDIO2, 142 VDD11, 143 VSS, 144 VDD
part B pins: 8 PC14-OSC32_IN, 9 PC15-OSC32_OUT, 26 PH0-OSC_IN, 27 PH1-OSC_OUT, 28 NRST, 107 PA13, 111 PA14, 112 PA15, 133 PB3, 134 PB4, 138 PH3-BOOT0
part C pins: 7 PC13, 29 PC0, 30 PC1, 31 PC2, 32 PC3, 36 PA0, 37 PA1, 38 PA2, 39 PA3, 42 PA4, 43 PA5, 44 PA6, 45 PA7, 46 PB0, 47 PB1, 48 PB2, 62 PB10, 63 PB11, 70 PB13, 71 PB14, 72 PB15, 98 PC6, 99 PC7, 100 PC8, 101 PC9, 102 PA8, 103 PA9, 104 PA10, 105 PA11, 106 PA12, 113 PC10, 114 PC11, 115 PC12, 135 PB5, 136 PB6, 137 PB7, 139 PB8, 140 PB9
part D pins: 1 PE2, 2 PE3, 3 PE4, 4 PE5, 5 PE6, 51 PE7, 52 PE8, 53 PE9, 56 PE10, 57 PE11, 58 PE12, 59 PE13, 60 PE14, 61 PE15, 73 PD8, 74 PD9, 75 PD10, 76 PD11, 77 PD12, 78 PD13, 79 PD14, 80 PD15, 116 PD0, 117 PD1, 118 PD2, 119 PD3, 120 PD4, 121 PD5, 123 PD6, 124 PD7, 141 PE0
part E pins: 10 PF0, 11 PF1, 12 PF2, 15 DSI_D0P, 16 DSI_D0N, 18 DSI_CKP, 19 DSI_CKN, 21 DSI_D1P, 22 DSI_D1N, 49 PG0, 50 PG1, 81 PH9, 84 PH10, 85 PH11, 86 PH12, 87 PH13, 90 PH14, 91 PH15, 92 PI0, 93 PI1, 96 PI2, 97 PI3, 125 PG9, 126 PG10, 127 PG12, 128 PG13, 129 PG14, 132 PG15
1 alternate drawing of the same symbol

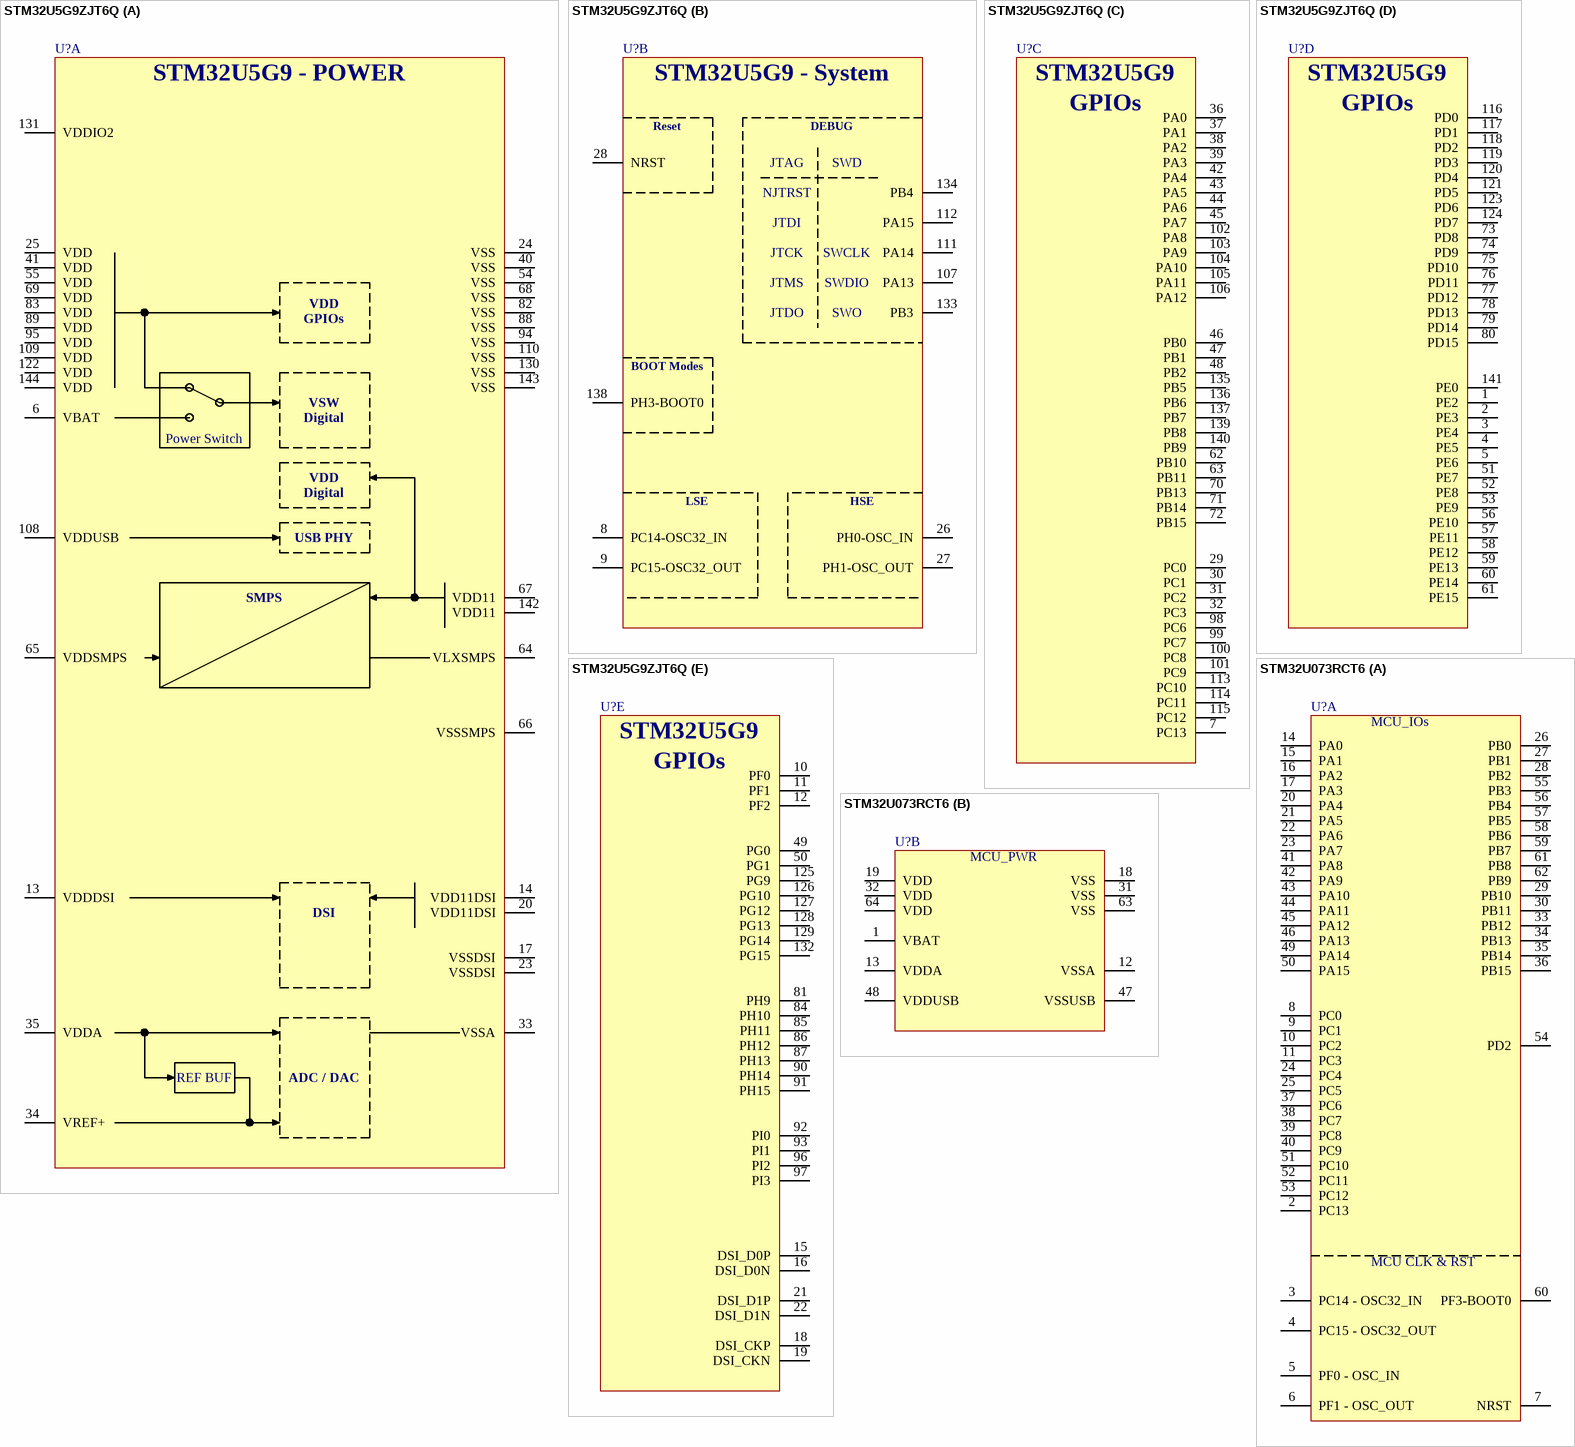
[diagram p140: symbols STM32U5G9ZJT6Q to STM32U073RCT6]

## STM32U5G9ZJT6Q
designator U?
part A pins: 6 VBAT, 13 VDDDSI, 14 VDD11DSI, 17 VSSDSI, 20 VDD11DSI, 23 VSSDSI, 24 VSS, 25 VDD, 33 VSSA, 34 VREF+, 35 VDDA, 40 VSS, 41 VDD, 54 VSS, 55 VDD, 64 VLXSMPS, 65 VDDSMPS, 66 VSSSMPS, 67 VDD11, 68 VSS, 69 VDD, 82 VSS, 83 VDD, 88 VSS, 89 VDD, 94 VSS, 95 VDD, 108 VDDUSB, 109 VDD, 110 VSS, 122 VDD, 130 VSS, 131 VDDIO2, 142 VDD11, 143 VSS, 144 VDD
part B pins: 8 PC14-OSC32_IN, 9 PC15-OSC32_OUT, 26 PH0-OSC_IN, 27 PH1-OSC_OUT, 28 NRST, 107 PA13, 111 PA14, 112 PA15, 133 PB3, 134 PB4, 138 PH3-BOOT0
part C pins: 7 PC13, 29 PC0, 30 PC1, 31 PC2, 32 PC3, 36 PA0, 37 PA1, 38 PA2, 39 PA3, 42 PA4, 43 PA5, 44 PA6, 45 PA7, 46 PB0, 47 PB1, 48 PB2, 62 PB10, 63 PB11, 70 PB13, 71 PB14, 72 PB15, 98 PC6, 99 PC7, 100 PC8, 101 PC9, 102 PA8, 103 PA9, 104 PA10, 105 PA11, 106 PA12, 113 PC10, 114 PC11, 115 PC12, 135 PB5, 136 PB6, 137 PB7, 139 PB8, 140 PB9
part D pins: 1 PE2, 2 PE3, 3 PE4, 4 PE5, 5 PE6, 51 PE7, 52 PE8, 53 PE9, 56 PE10, 57 PE11, 58 PE12, 59 PE13, 60 PE14, 61 PE15, 73 PD8, 74 PD9, 75 PD10, 76 PD11, 77 PD12, 78 PD13, 79 PD14, 80 PD15, 116 PD0, 117 PD1, 118 PD2, 119 PD3, 120 PD4, 121 PD5, 123 PD6, 124 PD7, 141 PE0
part E pins: 10 PF0, 11 PF1, 12 PF2, 15 DSI_D0P, 16 DSI_D0N, 18 DSI_CKP, 19 DSI_CKN, 21 DSI_D1P, 22 DSI_D1N, 49 PG0, 50 PG1, 81 PH9, 84 PH10, 85 PH11, 86 PH12, 87 PH13, 90 PH14, 91 PH15, 92 PI0, 93 PI1, 96 PI2, 97 PI3, 125 PG9, 126 PG10, 127 PG12, 128 PG13, 129 PG14, 132 PG15
1 alternate drawing of the same symbol

## STM32U073RCT6
designator U?
part A pins: 2 PC13, 3 PC14 - OSC32_IN, 4 PC15 - OSC32_OUT, 5 PF0 - OSC_IN, 6 PF1 - OSC_OUT, 7 NRST, 8 PC0, 9 PC1, 10 PC2, 11 PC3, 14 PA0, 15 PA1, 16 PA2, 17 PA3, 20 PA4, 21 PA5, 22 PA6, 23 PA7, 24 PC4, 25 PC5, 26 PB0, 27 PB1, 28 PB2, 29 PB10, 30 PB11, 33 PB12, 34 PB13, 35 PB14, 36 PB15, 37 PC6, 38 PC7, 39 PC8, 40 PC9, 41 PA8, 42 PA9, 43 PA10, 44 PA11, 45 PA12, 46 PA13, 49 PA14, 50 PA15, 51 PC10, 52 PC11, 53 PC12, 54 PD2, 55 PB3, 56 PB4, 57 PB5, 58 PB6, 59 PB7, 60 PF3-BOOT0, 61 PB8, 62 PB9
part B pins: 1 VBAT, 12 VSSA, 13 VDDA, 18 VSS, 19 VDD, 31 VSS, 32 VDD, 47 VSSUSB, 48 VDDUSB, 63 VSS, 64 VDD

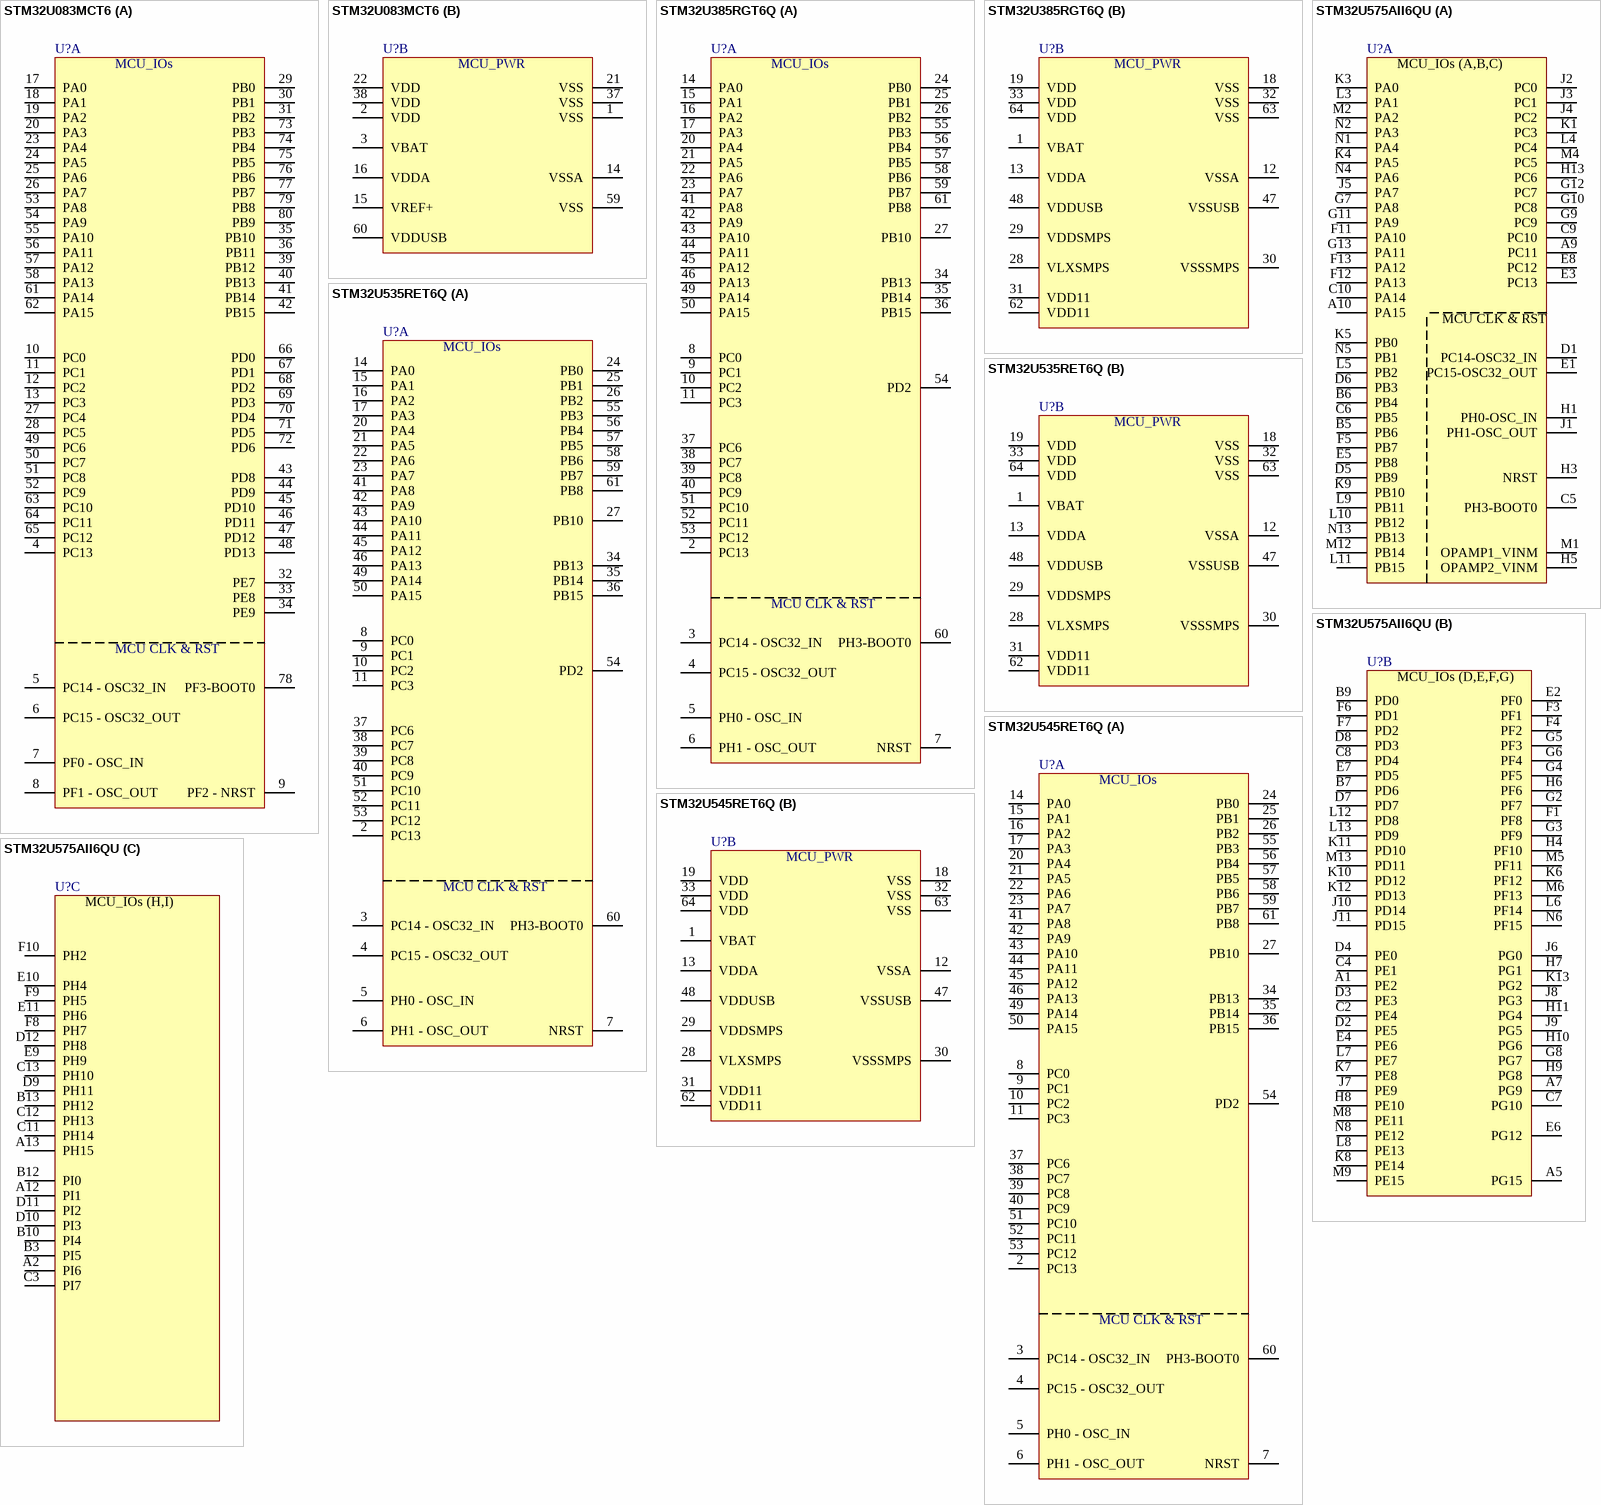
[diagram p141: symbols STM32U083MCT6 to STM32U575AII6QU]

## STM32U083MCT6
designator U?
part A pins: 4 PC13, 5 PC14 - OSC32_IN, 6 PC15 - OSC32_OUT, 7 PF0 - OSC_IN, 8 PF1 - OSC_OUT, 9 PF2 - NRST, 10 PC0, 11 PC1, 12 PC2, 13 PC3, 17 PA0, 18 PA1, 19 PA2, 20 PA3, 23 PA4, 24 PA5, 25 PA6, 26 PA7, 27 PC4, 28 PC5, 29 PB0, 30 PB1, 31 PB2, 32 PE7, 33 PE8, 34 PE9, 35 PB10, 36 PB11, 39 PB12, 40 PB13, 41 PB14, 42 PB15, 43 PD8, 44 PD9, 45 PD10, 46 PD11, 47 PD12, 48 PD13, 49 PC6, 50 PC7, 51 PC8, 52 PC9, 53 PA8, 54 PA9, 55 PA10, 56 PA11, 57 PA12, 58 PA13, 61 PA14, 62 PA15, 63 PC10, 64 PC11, 65 PC12, 66 PD0, 67 PD1, 68 PD2, 69 PD3, 70 PD4, 71 PD5, 72 PD6, 73 PB3, 74 PB4, 75 PB5, 76 PB6, 77 PB7, 78 PF3-BOOT0, 79 PB8, 80 PB9
part B pins: 1 VSS, 2 VDD, 3 VBAT, 14 VSSA, 15 VREF+, 16 VDDA, 21 VSS, 22 VDD, 37 VSS, 38 VDD, 59 VSS, 60 VDDUSB

## STM32U385RGT6Q
designator U?
part A pins: 2 PC13, 3 PC14 - OSC32_IN, 4 PC15 - OSC32_OUT, 5 PH0 - OSC_IN, 6 PH1 - OSC_OUT, 7 NRST, 8 PC0, 9 PC1, 10 PC2, 11 PC3, 14 PA0, 15 PA1, 16 PA2, 17 PA3, 20 PA4, 21 PA5, 22 PA6, 23 PA7, 24 PB0, 25 PB1, 26 PB2, 27 PB10, 34 PB13, 35 PB14, 36 PB15, 37 PC6, 38 PC7, 39 PC8, 40 PC9, 41 PA8, 42 PA9, 43 PA10, 44 PA11, 45 PA12, 46 PA13, 49 PA14, 50 PA15, 51 PC10, 52 PC11, 53 PC12, 54 PD2, 55 PB3, 56 PB4, 57 PB5, 58 PB6, 59 PB7, 60 PH3-BOOT0, 61 PB8
part B pins: 1 VBAT, 12 VSSA, 13 VDDA, 18 VSS, 19 VDD, 28 VLXSMPS, 29 VDDSMPS, 30 VSSSMPS, 31 VDD11, 32 VSS, 33 VDD, 47 VSSUSB, 48 VDDUSB, 62 VDD11, 63 VSS, 64 VDD

## STM32U535RET6Q
designator U?
part A pins: 2 PC13, 3 PC14 - OSC32_IN, 4 PC15 - OSC32_OUT, 5 PH0 - OSC_IN, 6 PH1 - OSC_OUT, 7 NRST, 8 PC0, 9 PC1, 10 PC2, 11 PC3, 14 PA0, 15 PA1, 16 PA2, 17 PA3, 20 PA4, 21 PA5, 22 PA6, 23 PA7, 24 PB0, 25 PB1, 26 PB2, 27 PB10, 34 PB13, 35 PB14, 36 PB15, 37 PC6, 38 PC7, 39 PC8, 40 PC9, 41 PA8, 42 PA9, 43 PA10, 44 PA11, 45 PA12, 46 PA13, 49 PA14, 50 PA15, 51 PC10, 52 PC11, 53 PC12, 54 PD2, 55 PB3, 56 PB4, 57 PB5, 58 PB6, 59 PB7, 60 PH3-BOOT0, 61 PB8
part B pins: 1 VBAT, 12 VSSA, 13 VDDA, 18 VSS, 19 VDD, 28 VLXSMPS, 29 VDDSMPS, 30 VSSSMPS, 31 VDD11, 32 VSS, 33 VDD, 47 VSSUSB, 48 VDDUSB, 62 VDD11, 63 VSS, 64 VDD

## STM32U545RET6Q
designator U?
part A pins: 2 PC13, 3 PC14 - OSC32_IN, 4 PC15 - OSC32_OUT, 5 PH0 - OSC_IN, 6 PH1 - OSC_OUT, 7 NRST, 8 PC0, 9 PC1, 10 PC2, 11 PC3, 14 PA0, 15 PA1, 16 PA2, 17 PA3, 20 PA4, 21 PA5, 22 PA6, 23 PA7, 24 PB0, 25 PB1, 26 PB2, 27 PB10, 34 PB13, 35 PB14, 36 PB15, 37 PC6, 38 PC7, 39 PC8, 40 PC9, 41 PA8, 42 PA9, 43 PA10, 44 PA11, 45 PA12, 46 PA13, 49 PA14, 50 PA15, 51 PC10, 52 PC11, 53 PC12, 54 PD2, 55 PB3, 56 PB4, 57 PB5, 58 PB6, 59 PB7, 60 PH3-BOOT0, 61 PB8
part B pins: 1 VBAT, 12 VSSA, 13 VDDA, 18 VSS, 19 VDD, 28 VLXSMPS, 29 VDDSMPS, 30 VSSSMPS, 31 VDD11, 32 VSS, 33 VDD, 47 VSSUSB, 48 VDDUSB, 62 VDD11, 63 VSS, 64 VDD

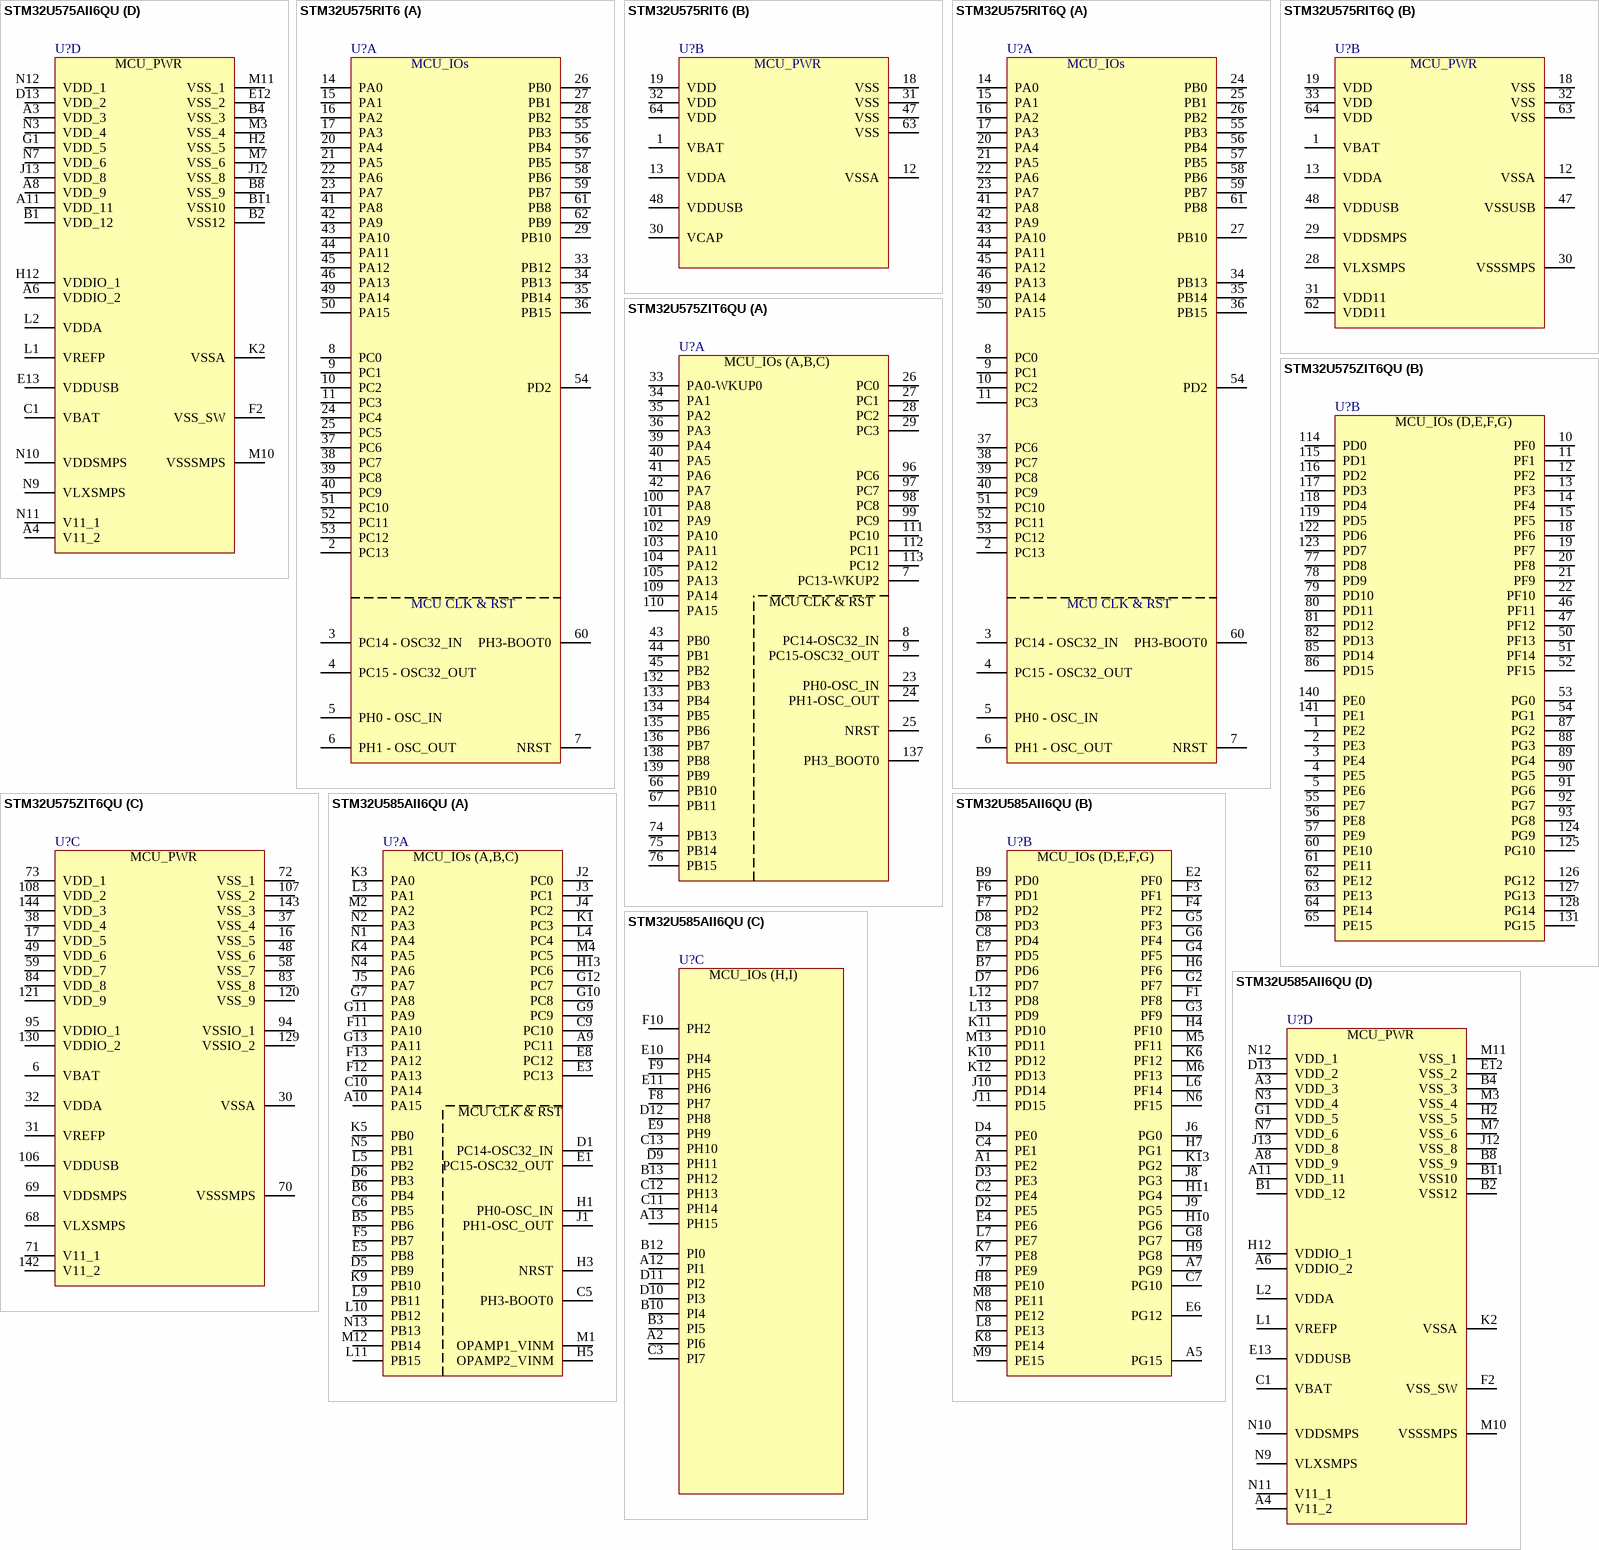
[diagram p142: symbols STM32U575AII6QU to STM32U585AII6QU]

## STM32U575AII6QU
designator U?
part A pins: A9 PC11, A10 PA15, B5 PB6, B6 PB4, C5 PH3-BOOT0, C6 PB5, C9 PC10, C10 PA14, D1 PC14-OSC32_IN, D5 PB9, D6 PB3, E1 PC15-OSC32_OUT, E3 PC13, E5 PB8, E8 PC12, F5 PB7, F11 PA10, F12 PA13, F13 PA12, G7 PA8, G9 PC9, G10 PC8, G11 PA9, G12 PC7, G13 PA11, H1 PH0-OSC_IN, H3 NRST, H5 OPAMP2_VINM, H13 PC6, J1 PH1-OSC_OUT, J2 PC0, J3 PC1, J4 PC2, J5 PA7, K1 PC3, K3 PA0, K4 PA5, K5 PB0, K9 PB10, L3 PA1, L4 PC4, L5 PB2, L9 PB11, L10 PB12, L11 PB15, M1 OPAMP1_VINM, M2 PA2, M4 PC5, M12 PB14, N1 PA4, N2 PA3, N4 PA6, N5 PB1, N13 PB13
part B pins: A1 PE2, A5 PG15, A7 PG9, B7 PD6, B9 PD0, C2 PE4, C4 PE1, C7 PG10, C8 PD4, D2 PE5, D3 PE3, D4 PE0, D7 PD7, D8 PD3, E2 PF0, E4 PE6, E6 PG12, E7 PD5, F1 PF8, F3 PF1, F4 PF2, F6 PD1, F7 PD2, G2 PF7, G3 PF9, G4 PF5, G5 PF3, G6 PF4, G8 PG7, H4 PF10, H6 PF6, H7 PG1, H8 PE10, H9 PG8, H10 PG6, H11 PG4, J6 PG0, J7 PE9, J8 PG3, J9 PG5, J10 PD14, J11 PD15, K6 PF12, K7 PE8, K8 PE14, K10 PD12, K11 PD10, K12 PD13, K13 PG2, L6 PF14, L7 PE7, L8 PE13, L12 PD8, L13 PD9, M5 PF11, M6 PF13, M8 PE11, M9 PE15, M13 PD11, N6 PF15, N8 PE12
part C pins: A2 PI6, A12 PI1, A13 PH15, B3 PI5, B10 PI4, B12 PI0, B13 PH12, C3 PI7, C11 PH14, C12 PH13, C13 PH10, D9 PH11, D10 PI3, D11 PI2, D12 PH8, E9 PH9, E10 PH4, E11 PH6, F8 PH7, F9 PH5, F10 PH2
part D pins: A3 VDD_3, A4 V11_2, A6 VDDIO_2, A8 VDD_9, A11 VDD_11, B1 VDD_12, B2 VSS12, B4 VSS_3, B8 VSS_9, B11 VSS10, C1 VBAT, D13 VDD_2, E12 VSS_2, E13 VDDUSB, F2 VSS_SW, G1 VDD_5, H2 VSS_5, H12 VDDIO_1, J12 VSS_8, J13 VDD_8, K2 VSSA, L1 VREFP, L2 VDDA, M3 VSS_4, M7 VSS_6, M10 VSSSMPS, M11 VSS_1, N3 VDD_4, N7 VDD_6, N9 VLXSMPS, N10 VDDSMPS, N11 V11_1, N12 VDD_1

## STM32U575RIT6
designator U?
part A pins: 2 PC13, 3 PC14 - OSC32_IN, 4 PC15 - OSC32_OUT, 5 PH0 - OSC_IN, 6 PH1 - OSC_OUT, 7 NRST, 8 PC0, 9 PC1, 10 PC2, 11 PC3, 14 PA0, 15 PA1, 16 PA2, 17 PA3, 20 PA4, 21 PA5, 22 PA6, 23 PA7, 24 PC4, 25 PC5, 26 PB0, 27 PB1, 28 PB2, 29 PB10, 33 PB12, 34 PB13, 35 PB14, 36 PB15, 37 PC6, 38 PC7, 39 PC8, 40 PC9, 41 PA8, 42 PA9, 43 PA10, 44 PA11, 45 PA12, 46 PA13, 49 PA14, 50 PA15, 51 PC10, 52 PC11, 53 PC12, 54 PD2, 55 PB3, 56 PB4, 57 PB5, 58 PB6, 59 PB7, 60 PH3-BOOT0, 61 PB8, 62 PB9
part B pins: 1 VBAT, 12 VSSA, 13 VDDA, 18 VSS, 19 VDD, 30 VCAP, 31 VSS, 32 VDD, 47 VSS, 48 VDDUSB, 63 VSS, 64 VDD

## STM32U575RIT6Q
designator U?
part A pins: 2 PC13, 3 PC14 - OSC32_IN, 4 PC15 - OSC32_OUT, 5 PH0 - OSC_IN, 6 PH1 - OSC_OUT, 7 NRST, 8 PC0, 9 PC1, 10 PC2, 11 PC3, 14 PA0, 15 PA1, 16 PA2, 17 PA3, 20 PA4, 21 PA5, 22 PA6, 23 PA7, 24 PB0, 25 PB1, 26 PB2, 27 PB10, 34 PB13, 35 PB14, 36 PB15, 37 PC6, 38 PC7, 39 PC8, 40 PC9, 41 PA8, 42 PA9, 43 PA10, 44 PA11, 45 PA12, 46 PA13, 49 PA14, 50 PA15, 51 PC10, 52 PC11, 53 PC12, 54 PD2, 55 PB3, 56 PB4, 57 PB5, 58 PB6, 59 PB7, 60 PH3-BOOT0, 61 PB8
part B pins: 1 VBAT, 12 VSSA, 13 VDDA, 18 VSS, 19 VDD, 28 VLXSMPS, 29 VDDSMPS, 30 VSSSMPS, 31 VDD11, 32 VSS, 33 VDD, 47 VSSUSB, 48 VDDUSB, 62 VDD11, 63 VSS, 64 VDD

## STM32U575ZIT6QU
designator U?
part A pins: 7 PC13-WKUP2, 8 PC14-OSC32_IN, 9 PC15-OSC32_OUT, 23 PH0-OSC_IN, 24 PH1-OSC_OUT, 25 NRST, 26 PC0, 27 PC1, 28 PC2, 29 PC3, 33 PA0-WKUP0, 34 PA1, 35 PA2, 36 PA3, 39 PA4, 40 PA5, 41 PA6, 42 PA7, 43 PB0, 44 PB1, 45 PB2, 66 PB10, 67 PB11, 74 PB13, 75 PB14, 76 PB15, 96 PC6, 97 PC7, 98 PC8, 99 PC9, 100 PA8, 101 PA9, 102 PA10, 103 PA11, 104 PA12, 105 PA13, 109 PA14, 110 PA15, 111 PC10, 112 PC11, 113 PC12, 132 PB3, 133 PB4, 134 PB5, 135 PB6, 136 PB7, 137 PH3_BOOT0, 138 PB8, 139 PB9
part B pins: 1 PE2, 2 PE3, 3 PE4, 4 PE5, 5 PE6, 10 PF0, 11 PF1, 12 PF2, 13 PF3, 14 PF4, 15 PF5, 18 PF6, 19 PF7, 20 PF8, 21 PF9, 22 PF10, 46 PF11, 47 PF12, 50 PF13, 51 PF14, 52 PF15, 53 PG0, 54 PG1, 55 PE7, 56 PE8, 57 PE9, 60 PE10, 61 PE11, 62 PE12, 63 PE13, 64 PE14, 65 PE15, 77 PD8, 78 PD9, 79 PD10, 80 PD11, 81 PD12, 82 PD13, 85 PD14, 86 PD15, 87 PG2, 88 PG3, 89 PG4, 90 PG5, 91 PG6, 92 PG7, 93 PG8, 114 PD0, 115 PD1, 116 PD2, 117 PD3, 118 PD4, 119 PD5, 122 PD6, 123 PD7, 124 PG9, 125 PG10, 126 PG12, 127 PG13, 128 PG14, 131 PG15, 140 PE0, 141 PE1
part C pins: 6 VBAT, 16 VSS_5, 17 VDD_5, 30 VSSA, 31 VREFP, 32 VDDA, 37 VSS_4, 38 VDD_4, 48 VSS_6, 49 VDD_6, 58 VSS_7, 59 VDD_7, 68 VLXSMPS, 69 VDDSMPS, 70 VSSSMPS, 71 V11_1, 72 VSS_1, 73 VDD_1, 83 VSS_8, 84 VDD_8, 94 VSSIO_1, 95 VDDIO_1, 106 VDDUSB, 107 VSS_2, 108 VDD_2, 120 VSS_9, 121 VDD_9, 129 VSSIO_2, 130 VDDIO_2, 142 V11_2, 143 VSS_3, 144 VDD_3

## STM32U585AII6QU
designator U?
part A pins: A9 PC11, A10 PA15, B5 PB6, B6 PB4, C5 PH3-BOOT0, C6 PB5, C9 PC10, C10 PA14, D1 PC14-OSC32_IN, D5 PB9, D6 PB3, E1 PC15-OSC32_OUT, E3 PC13, E5 PB8, E8 PC12, F5 PB7, F11 PA10, F12 PA13, F13 PA12, G7 PA8, G9 PC9, G10 PC8, G11 PA9, G12 PC7, G13 PA11, H1 PH0-OSC_IN, H3 NRST, H5 OPAMP2_VINM, H13 PC6, J1 PH1-OSC_OUT, J2 PC0, J3 PC1, J4 PC2, J5 PA7, K1 PC3, K3 PA0, K4 PA5, K5 PB0, K9 PB10, L3 PA1, L4 PC4, L5 PB2, L9 PB11, L10 PB12, L11 PB15, M1 OPAMP1_VINM, M2 PA2, M4 PC5, M12 PB14, N1 PA4, N2 PA3, N4 PA6, N5 PB1, N13 PB13
part B pins: A1 PE2, A5 PG15, A7 PG9, B7 PD6, B9 PD0, C2 PE4, C4 PE1, C7 PG10, C8 PD4, D2 PE5, D3 PE3, D4 PE0, D7 PD7, D8 PD3, E2 PF0, E4 PE6, E6 PG12, E7 PD5, F1 PF8, F3 PF1, F4 PF2, F6 PD1, F7 PD2, G2 PF7, G3 PF9, G4 PF5, G5 PF3, G6 PF4, G8 PG7, H4 PF10, H6 PF6, H7 PG1, H8 PE10, H9 PG8, H10 PG6, H11 PG4, J6 PG0, J7 PE9, J8 PG3, J9 PG5, J10 PD14, J11 PD15, K6 PF12, K7 PE8, K8 PE14, K10 PD12, K11 PD10, K12 PD13, K13 PG2, L6 PF14, L7 PE7, L8 PE13, L12 PD8, L13 PD9, M5 PF11, M6 PF13, M8 PE11, M9 PE15, M13 PD11, N6 PF15, N8 PE12
part C pins: A2 PI6, A12 PI1, A13 PH15, B3 PI5, B10 PI4, B12 PI0, B13 PH12, C3 PI7, C11 PH14, C12 PH13, C13 PH10, D9 PH11, D10 PI3, D11 PI2, D12 PH8, E9 PH9, E10 PH4, E11 PH6, F8 PH7, F9 PH5, F10 PH2
part D pins: A3 VDD_3, A4 V11_2, A6 VDDIO_2, A8 VDD_9, A11 VDD_11, B1 VDD_12, B2 VSS12, B4 VSS_3, B8 VSS_9, B11 VSS10, C1 VBAT, D13 VDD_2, E12 VSS_2, E13 VDDUSB, F2 VSS_SW, G1 VDD_5, H2 VSS_5, H12 VDDIO_1, J12 VSS_8, J13 VDD_8, K2 VSSA, L1 VREFP, L2 VDDA, M3 VSS_4, M7 VSS_6, M10 VSSSMPS, M11 VSS_1, N3 VDD_4, N7 VDD_6, N9 VLXSMPS, N10 VDDSMPS, N11 V11_1, N12 VDD_1

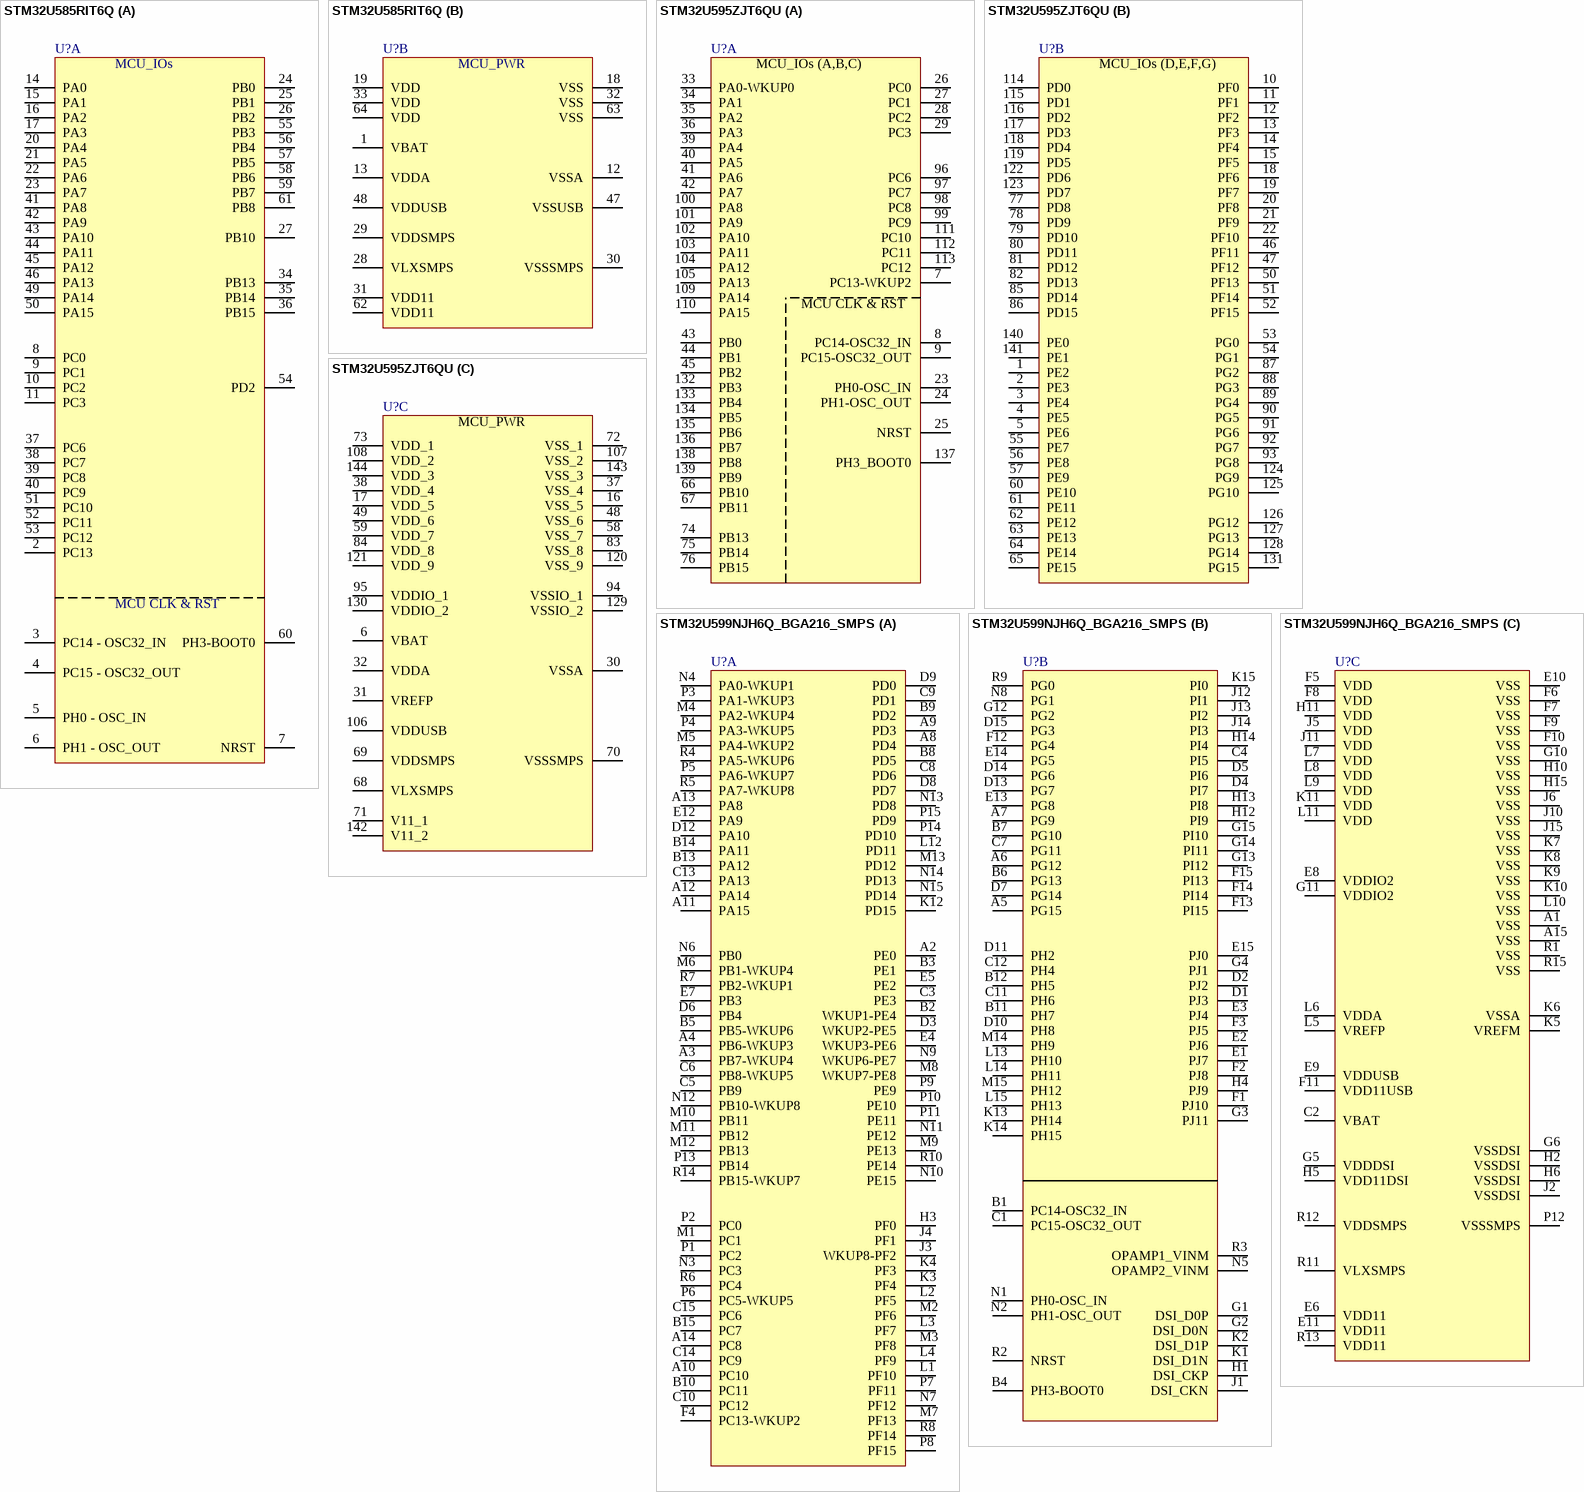
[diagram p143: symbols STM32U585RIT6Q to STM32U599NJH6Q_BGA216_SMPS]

## STM32U585RIT6Q
designator U?
part A pins: 2 PC13, 3 PC14 - OSC32_IN, 4 PC15 - OSC32_OUT, 5 PH0 - OSC_IN, 6 PH1 - OSC_OUT, 7 NRST, 8 PC0, 9 PC1, 10 PC2, 11 PC3, 14 PA0, 15 PA1, 16 PA2, 17 PA3, 20 PA4, 21 PA5, 22 PA6, 23 PA7, 24 PB0, 25 PB1, 26 PB2, 27 PB10, 34 PB13, 35 PB14, 36 PB15, 37 PC6, 38 PC7, 39 PC8, 40 PC9, 41 PA8, 42 PA9, 43 PA10, 44 PA11, 45 PA12, 46 PA13, 49 PA14, 50 PA15, 51 PC10, 52 PC11, 53 PC12, 54 PD2, 55 PB3, 56 PB4, 57 PB5, 58 PB6, 59 PB7, 60 PH3-BOOT0, 61 PB8
part B pins: 1 VBAT, 12 VSSA, 13 VDDA, 18 VSS, 19 VDD, 28 VLXSMPS, 29 VDDSMPS, 30 VSSSMPS, 31 VDD11, 32 VSS, 33 VDD, 47 VSSUSB, 48 VDDUSB, 62 VDD11, 63 VSS, 64 VDD

## STM32U595ZJT6QU
designator U?
part A pins: 7 PC13-WKUP2, 8 PC14-OSC32_IN, 9 PC15-OSC32_OUT, 23 PH0-OSC_IN, 24 PH1-OSC_OUT, 25 NRST, 26 PC0, 27 PC1, 28 PC2, 29 PC3, 33 PA0-WKUP0, 34 PA1, 35 PA2, 36 PA3, 39 PA4, 40 PA5, 41 PA6, 42 PA7, 43 PB0, 44 PB1, 45 PB2, 66 PB10, 67 PB11, 74 PB13, 75 PB14, 76 PB15, 96 PC6, 97 PC7, 98 PC8, 99 PC9, 100 PA8, 101 PA9, 102 PA10, 103 PA11, 104 PA12, 105 PA13, 109 PA14, 110 PA15, 111 PC10, 112 PC11, 113 PC12, 132 PB3, 133 PB4, 134 PB5, 135 PB6, 136 PB7, 137 PH3_BOOT0, 138 PB8, 139 PB9
part B pins: 1 PE2, 2 PE3, 3 PE4, 4 PE5, 5 PE6, 10 PF0, 11 PF1, 12 PF2, 13 PF3, 14 PF4, 15 PF5, 18 PF6, 19 PF7, 20 PF8, 21 PF9, 22 PF10, 46 PF11, 47 PF12, 50 PF13, 51 PF14, 52 PF15, 53 PG0, 54 PG1, 55 PE7, 56 PE8, 57 PE9, 60 PE10, 61 PE11, 62 PE12, 63 PE13, 64 PE14, 65 PE15, 77 PD8, 78 PD9, 79 PD10, 80 PD11, 81 PD12, 82 PD13, 85 PD14, 86 PD15, 87 PG2, 88 PG3, 89 PG4, 90 PG5, 91 PG6, 92 PG7, 93 PG8, 114 PD0, 115 PD1, 116 PD2, 117 PD3, 118 PD4, 119 PD5, 122 PD6, 123 PD7, 124 PG9, 125 PG10, 126 PG12, 127 PG13, 128 PG14, 131 PG15, 140 PE0, 141 PE1
part C pins: 6 VBAT, 16 VSS_5, 17 VDD_5, 30 VSSA, 31 VREFP, 32 VDDA, 37 VSS_4, 38 VDD_4, 48 VSS_6, 49 VDD_6, 58 VSS_7, 59 VDD_7, 68 VLXSMPS, 69 VDDSMPS, 70 VSSSMPS, 71 V11_1, 72 VSS_1, 73 VDD_1, 83 VSS_8, 84 VDD_8, 94 VSSIO_1, 95 VDDIO_1, 106 VDDUSB, 107 VSS_2, 108 VDD_2, 120 VSS_9, 121 VDD_9, 129 VSSIO_2, 130 VDDIO_2, 142 V11_2, 143 VSS_3, 144 VDD_3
